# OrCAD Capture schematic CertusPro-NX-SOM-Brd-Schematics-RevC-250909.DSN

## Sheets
1 Title Page: title: Title Page; rev: 2.0; note: 305-PD-25-0961
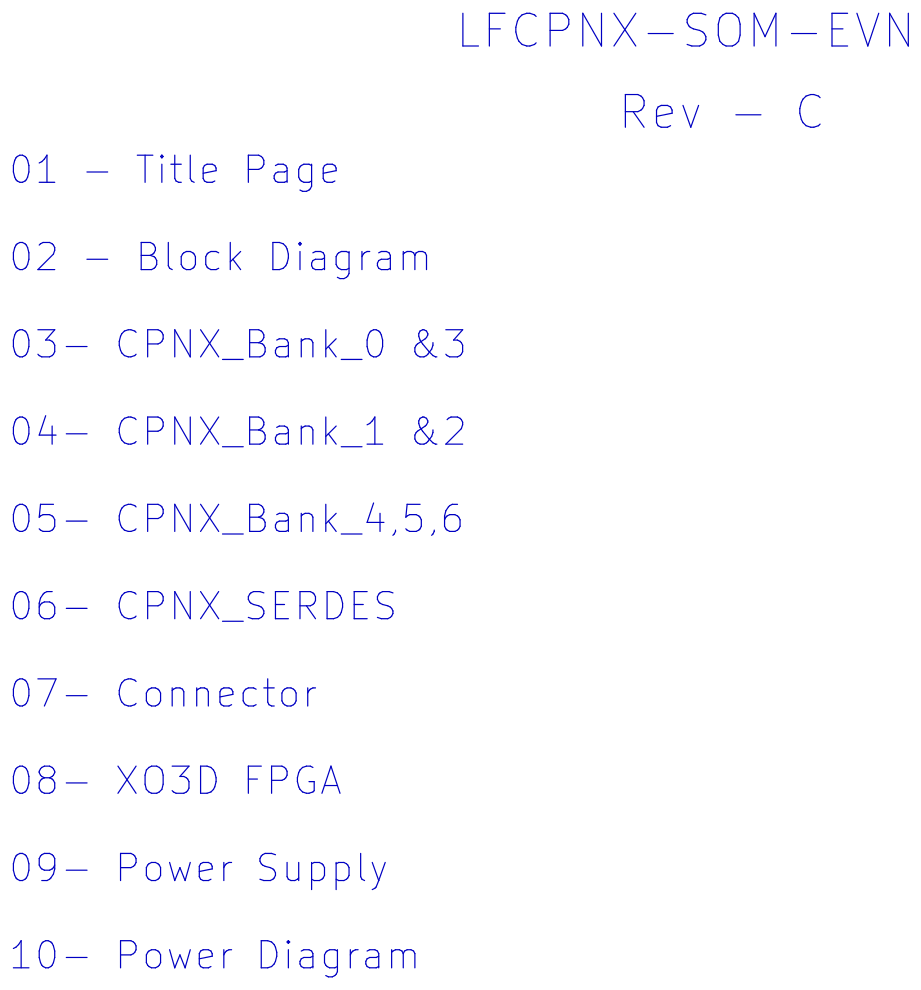
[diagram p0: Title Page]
2 Block Diagram: title: Block Diagram
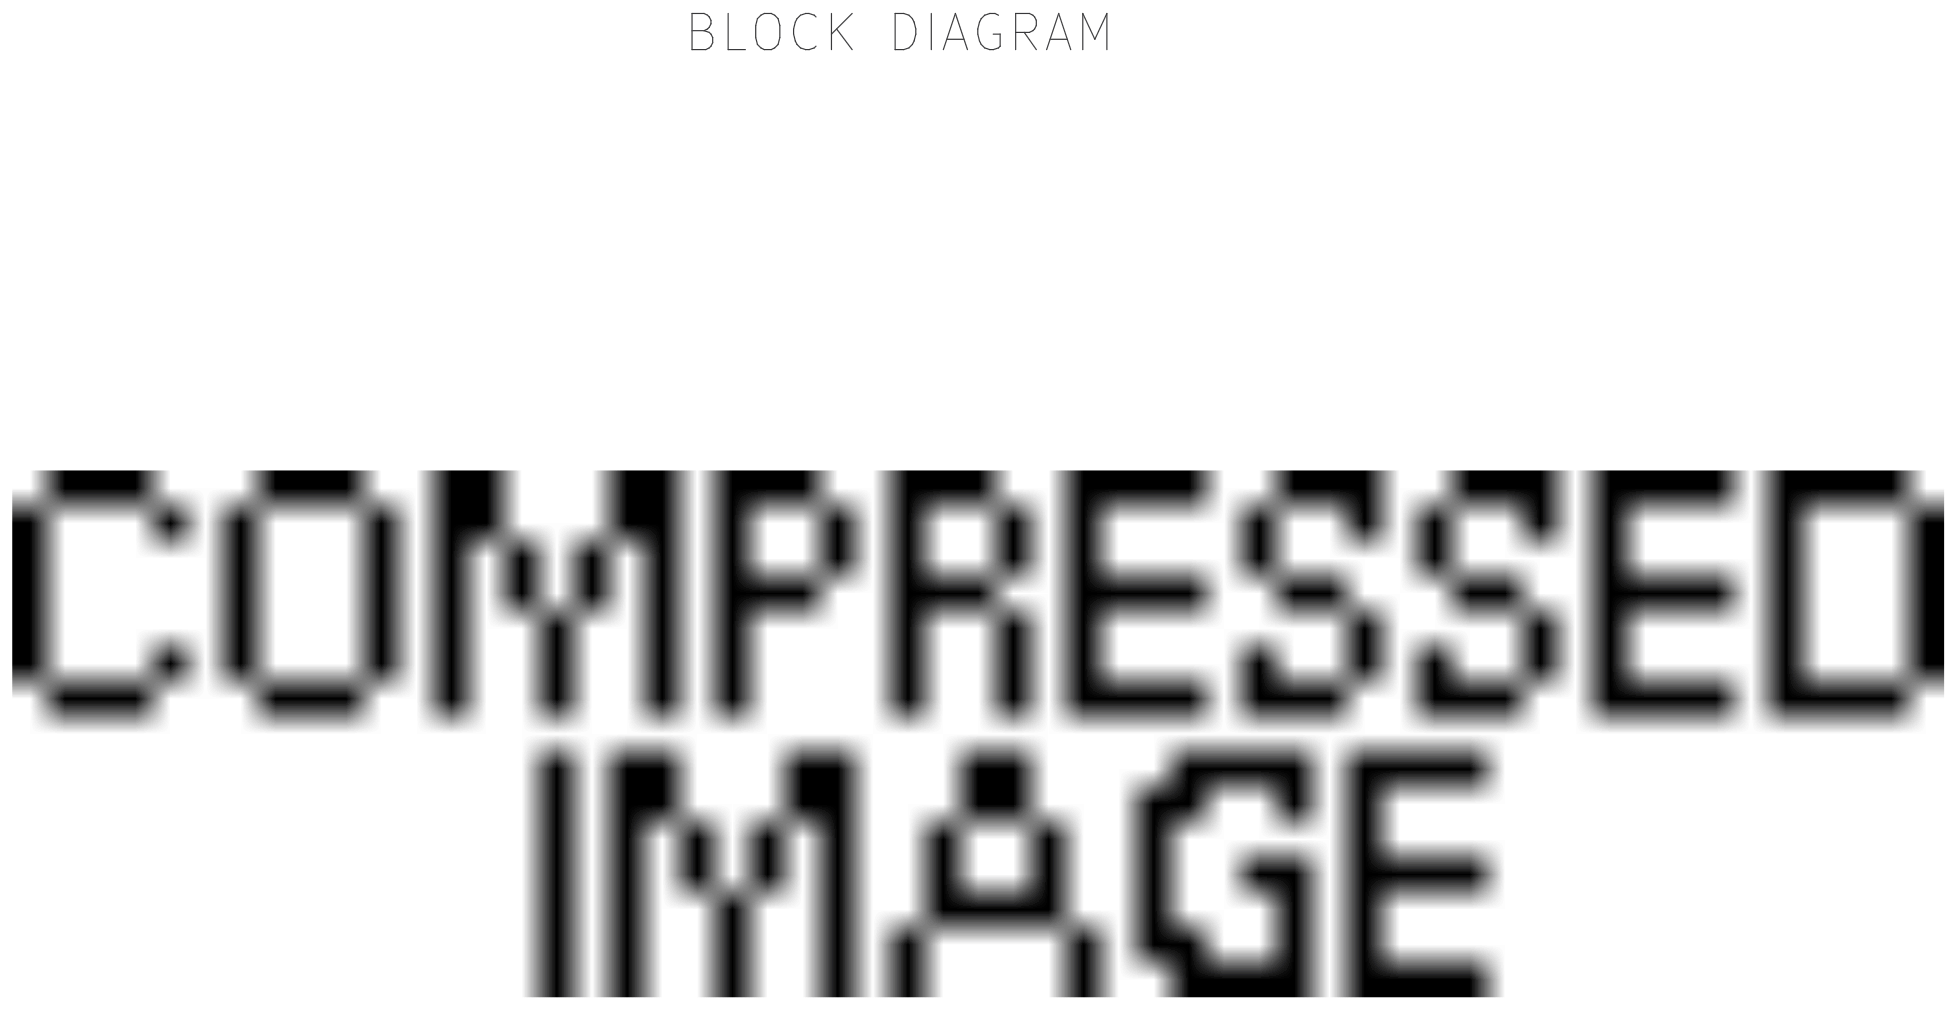
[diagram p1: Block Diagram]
3 CPNX_Bank_0: size B; title: CPNX_Bank_0_Config
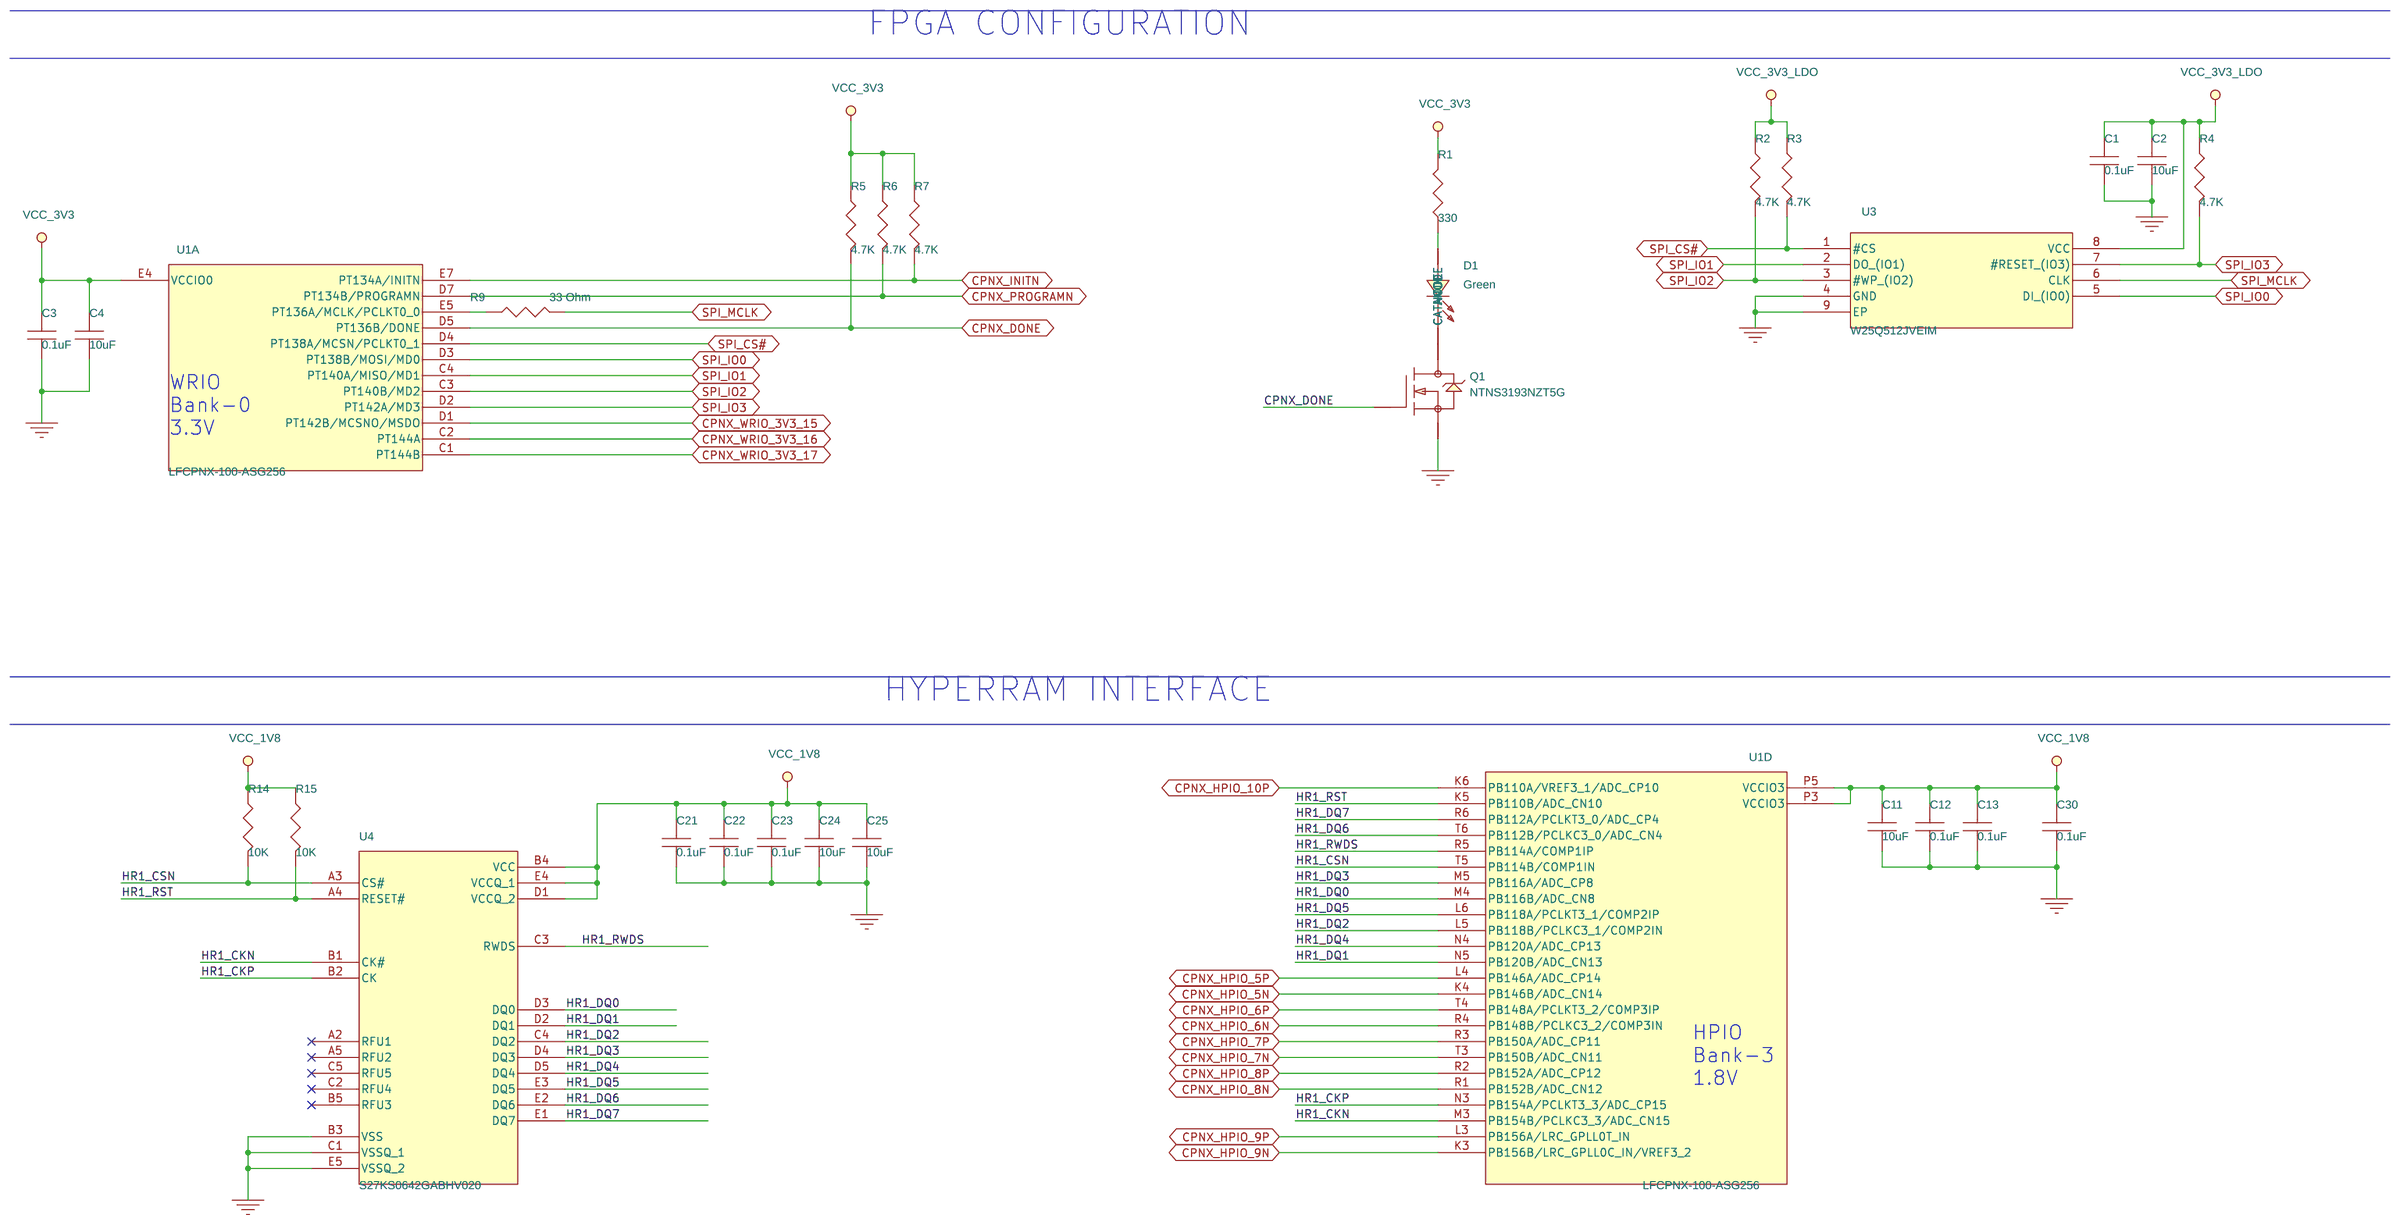
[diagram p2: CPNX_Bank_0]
4 CPNX_Bank_0,1,2: size B; title: CPNX JTAG GPIO
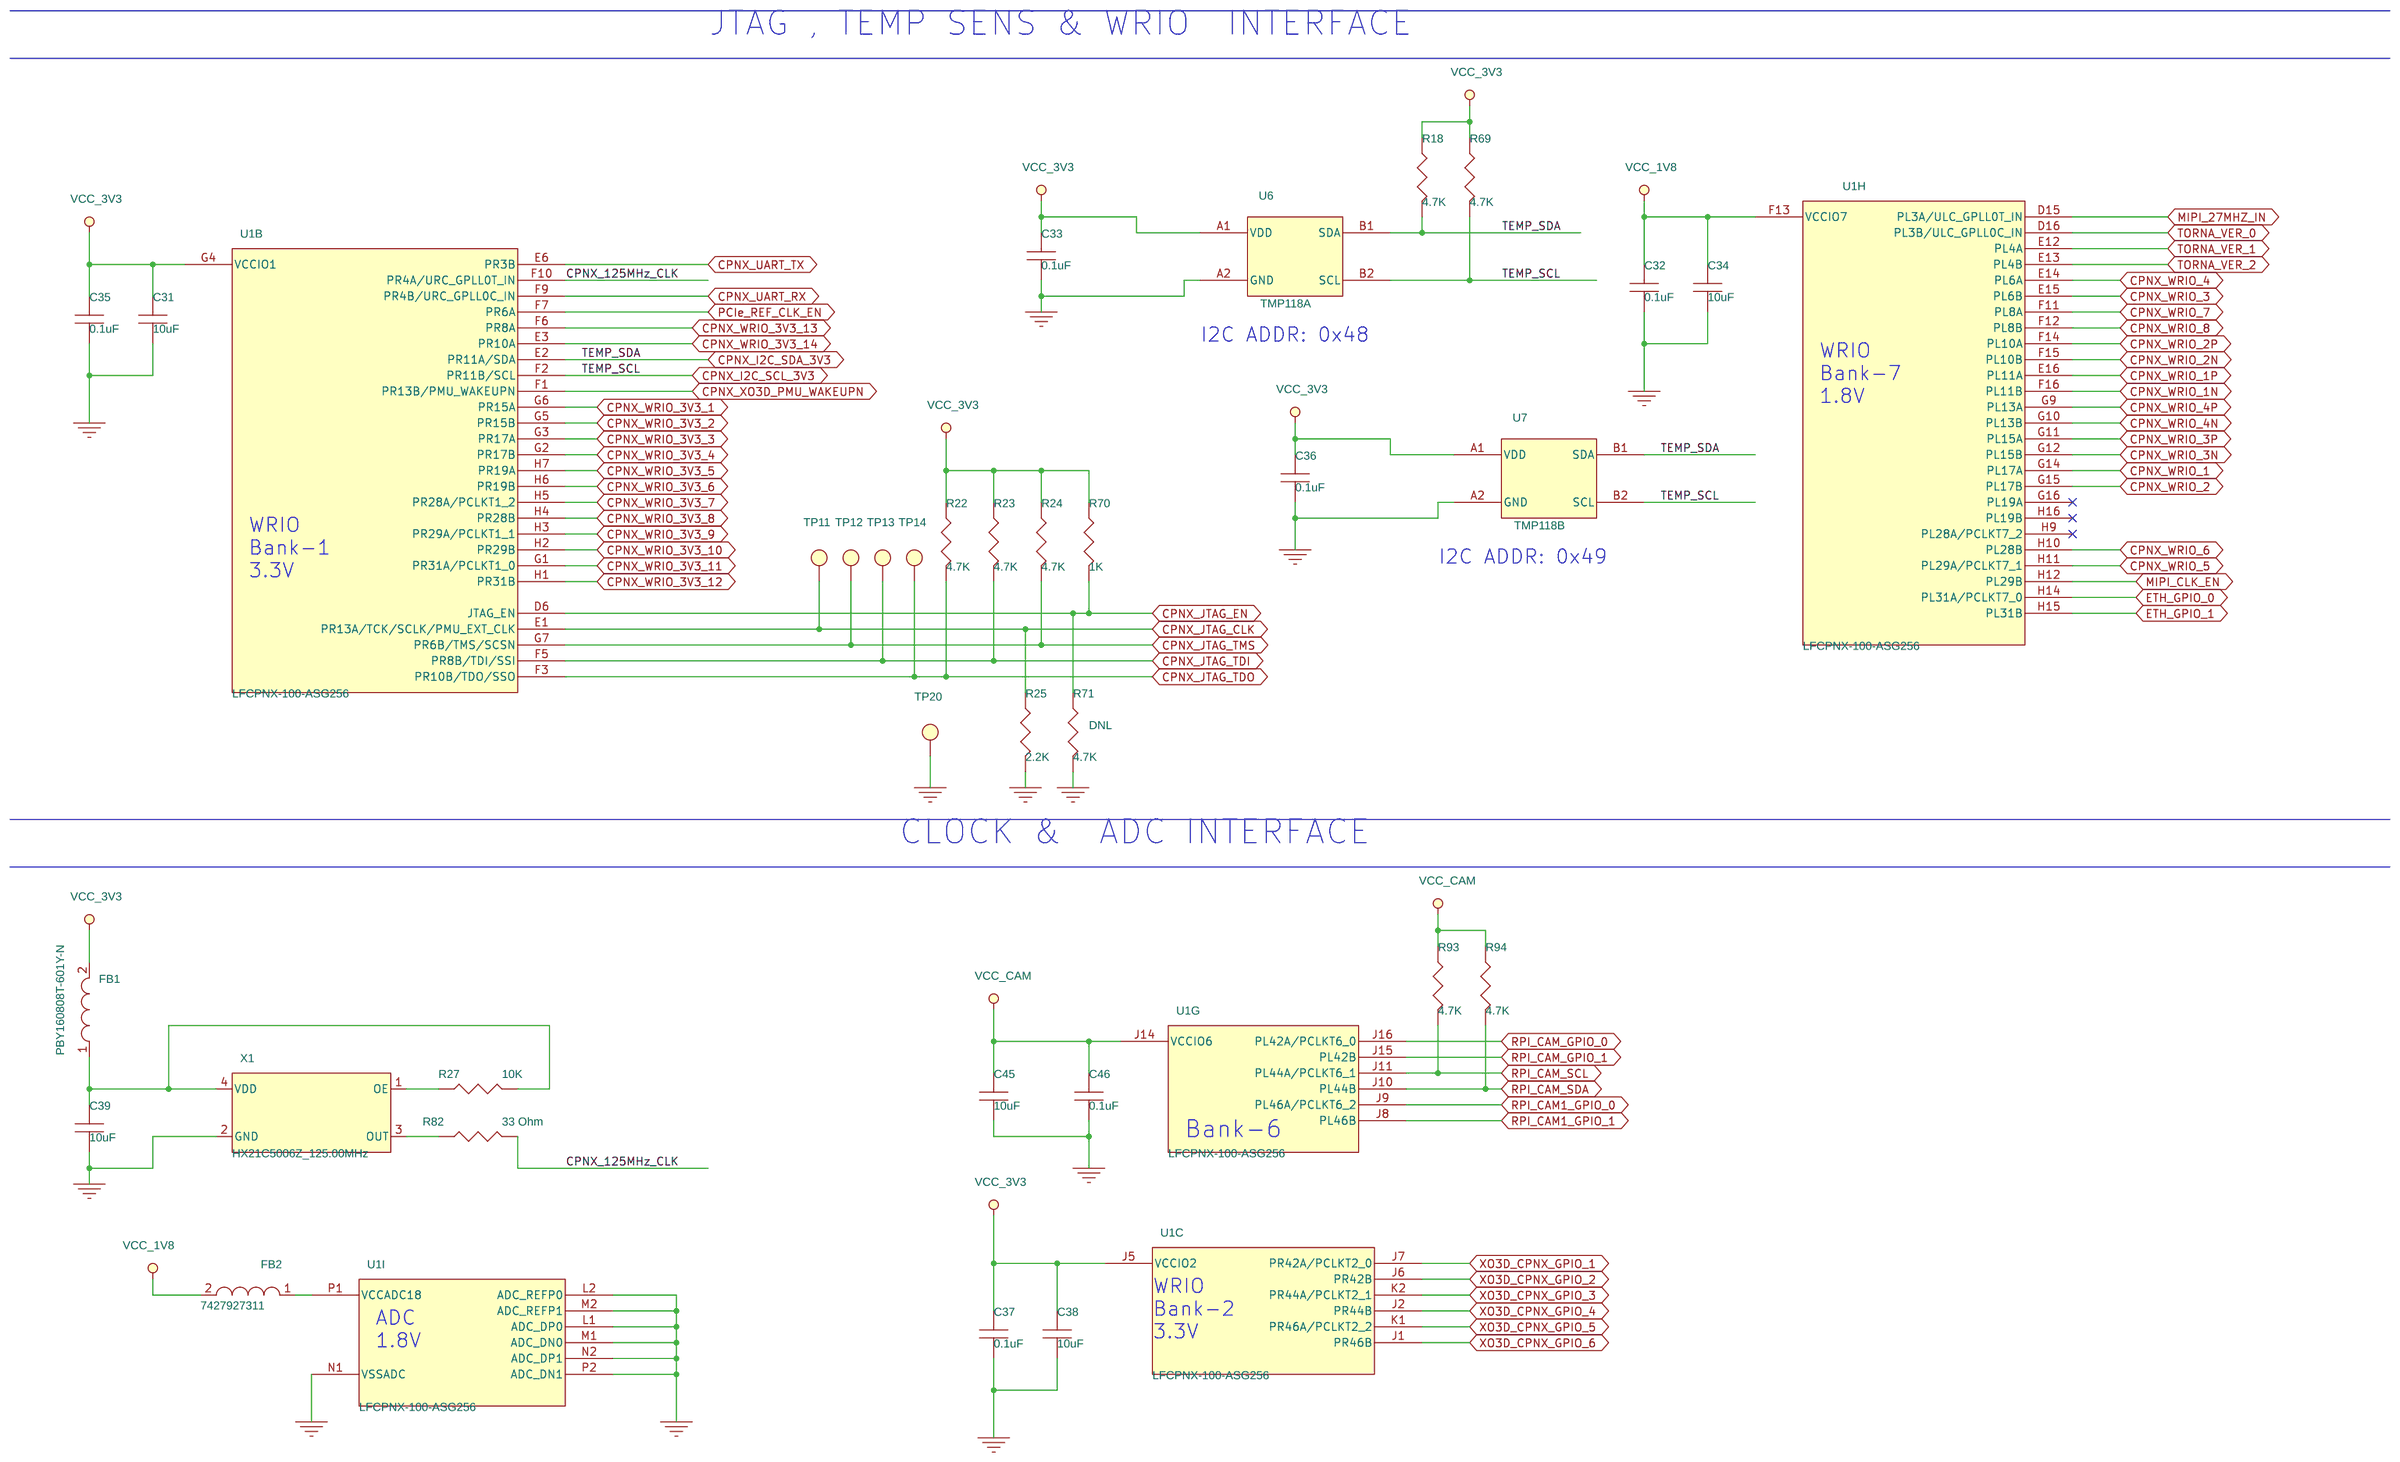
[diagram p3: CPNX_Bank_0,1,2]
5 CPNX_Bank-4 ,5 ,6: size B; title: RPC DRAM's
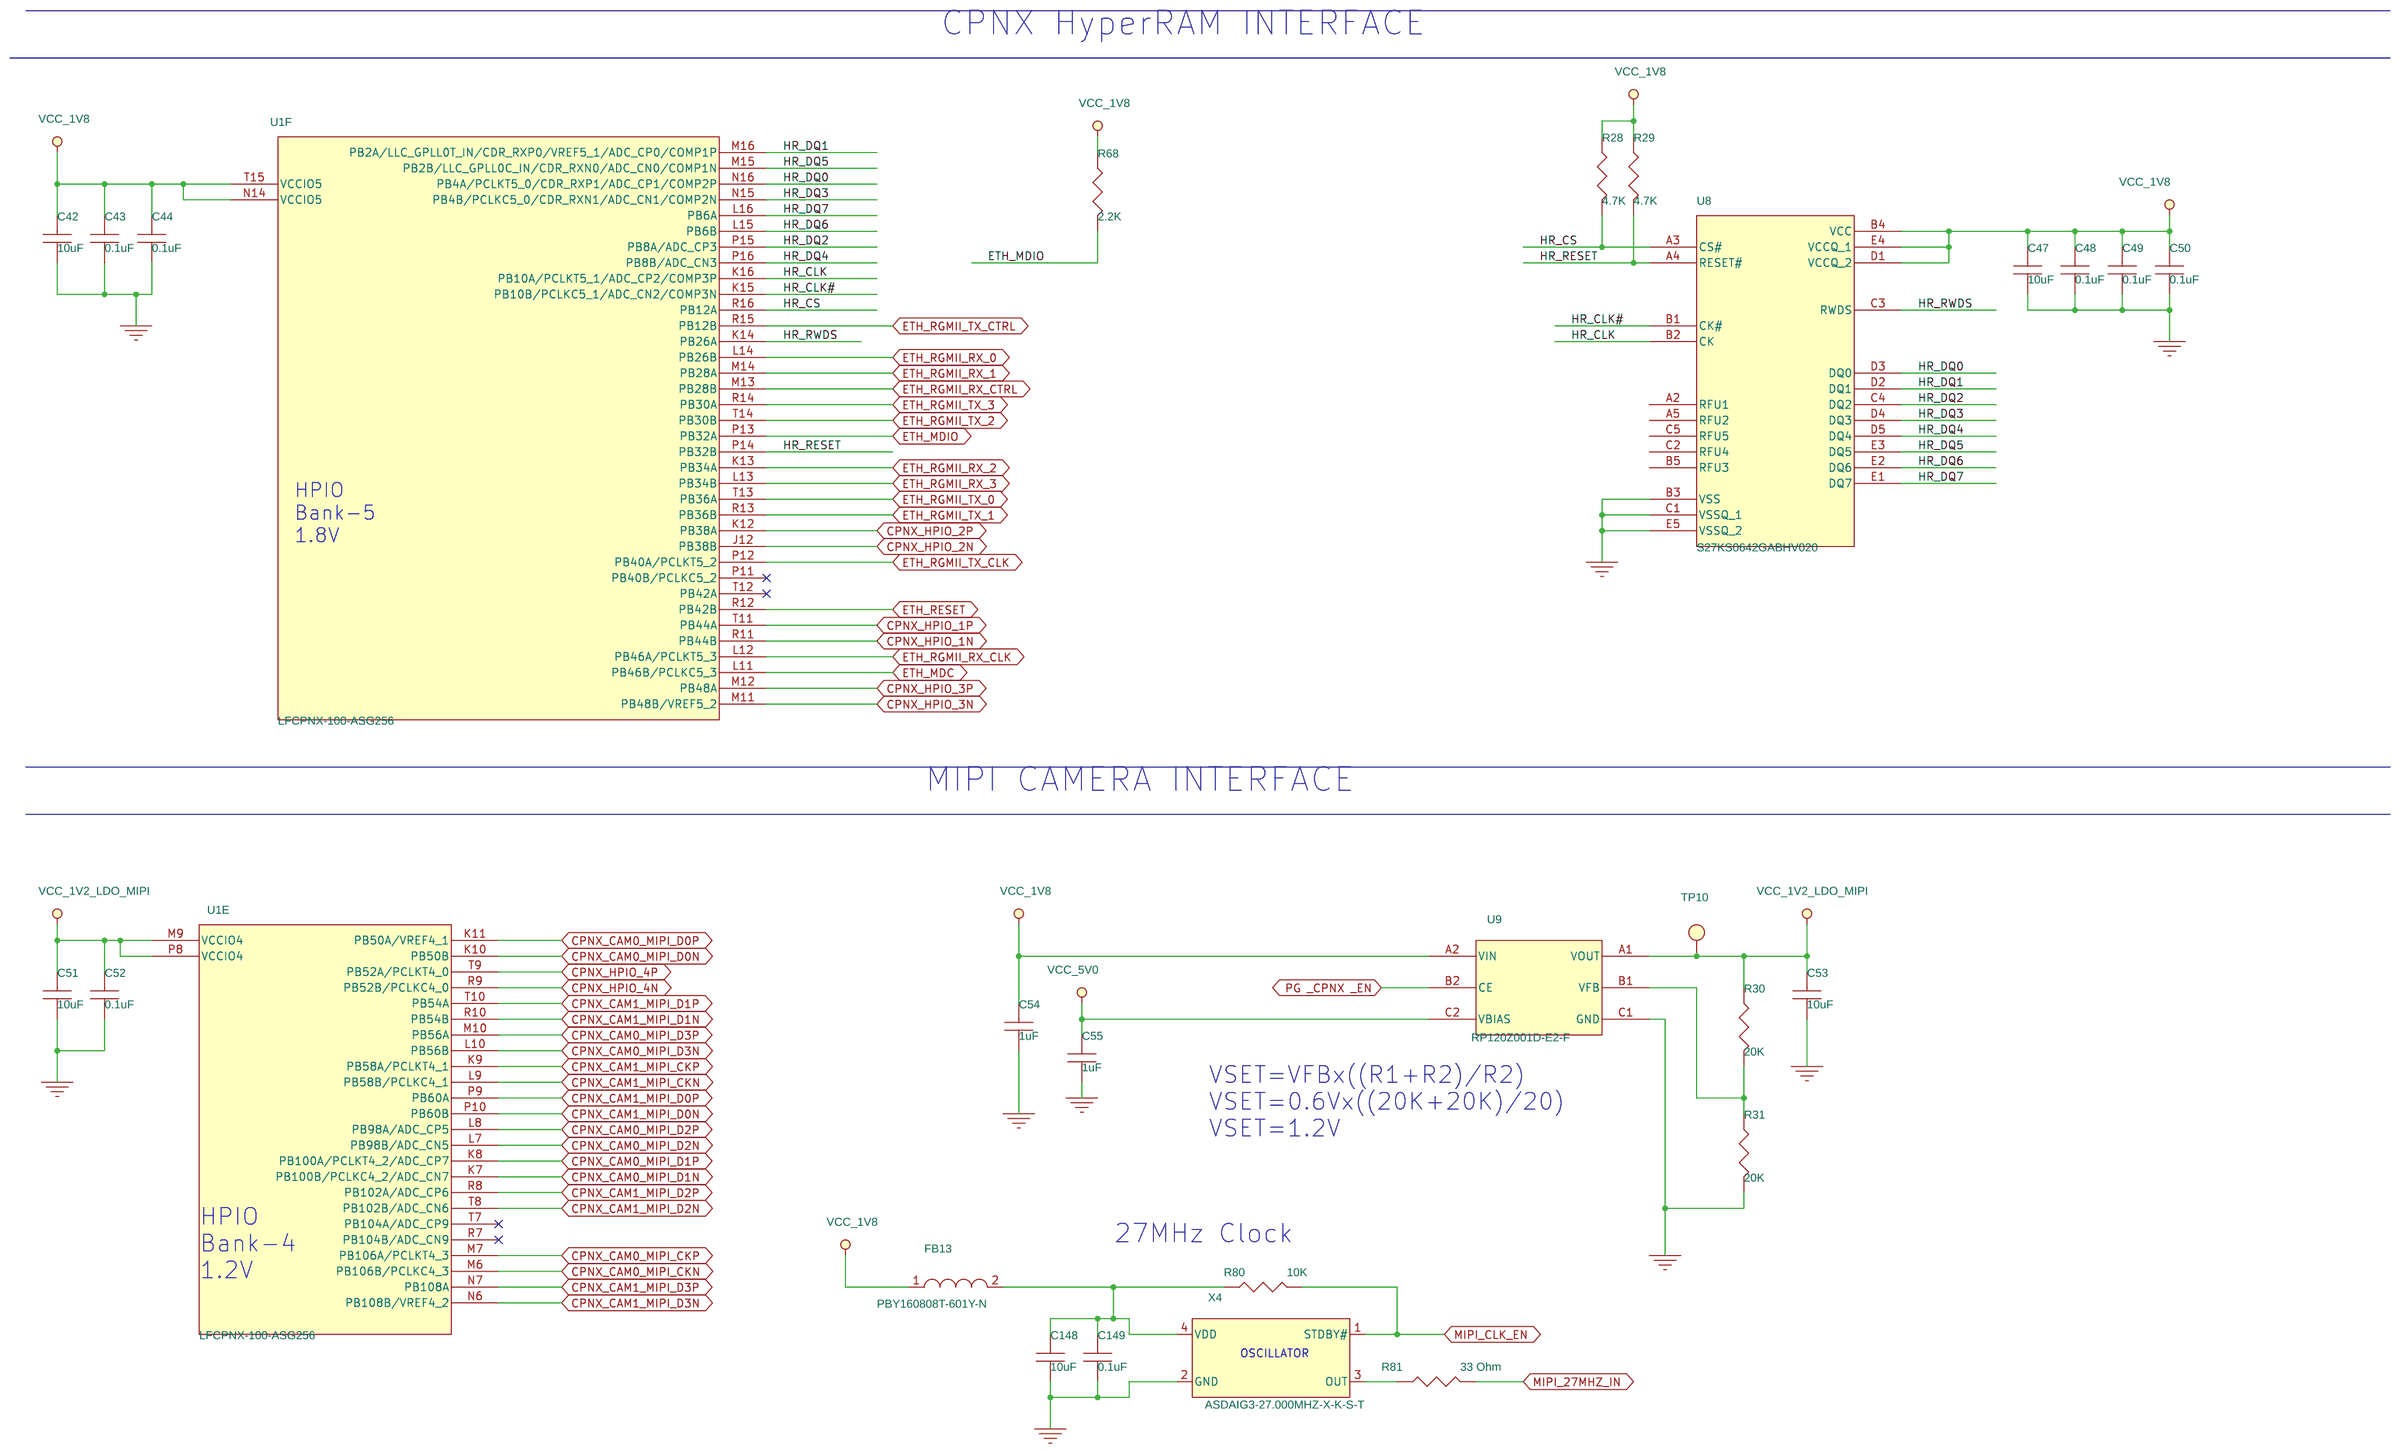
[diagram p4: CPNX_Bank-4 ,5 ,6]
6 CPNX SERDES: size B; title: CPNX SERDES
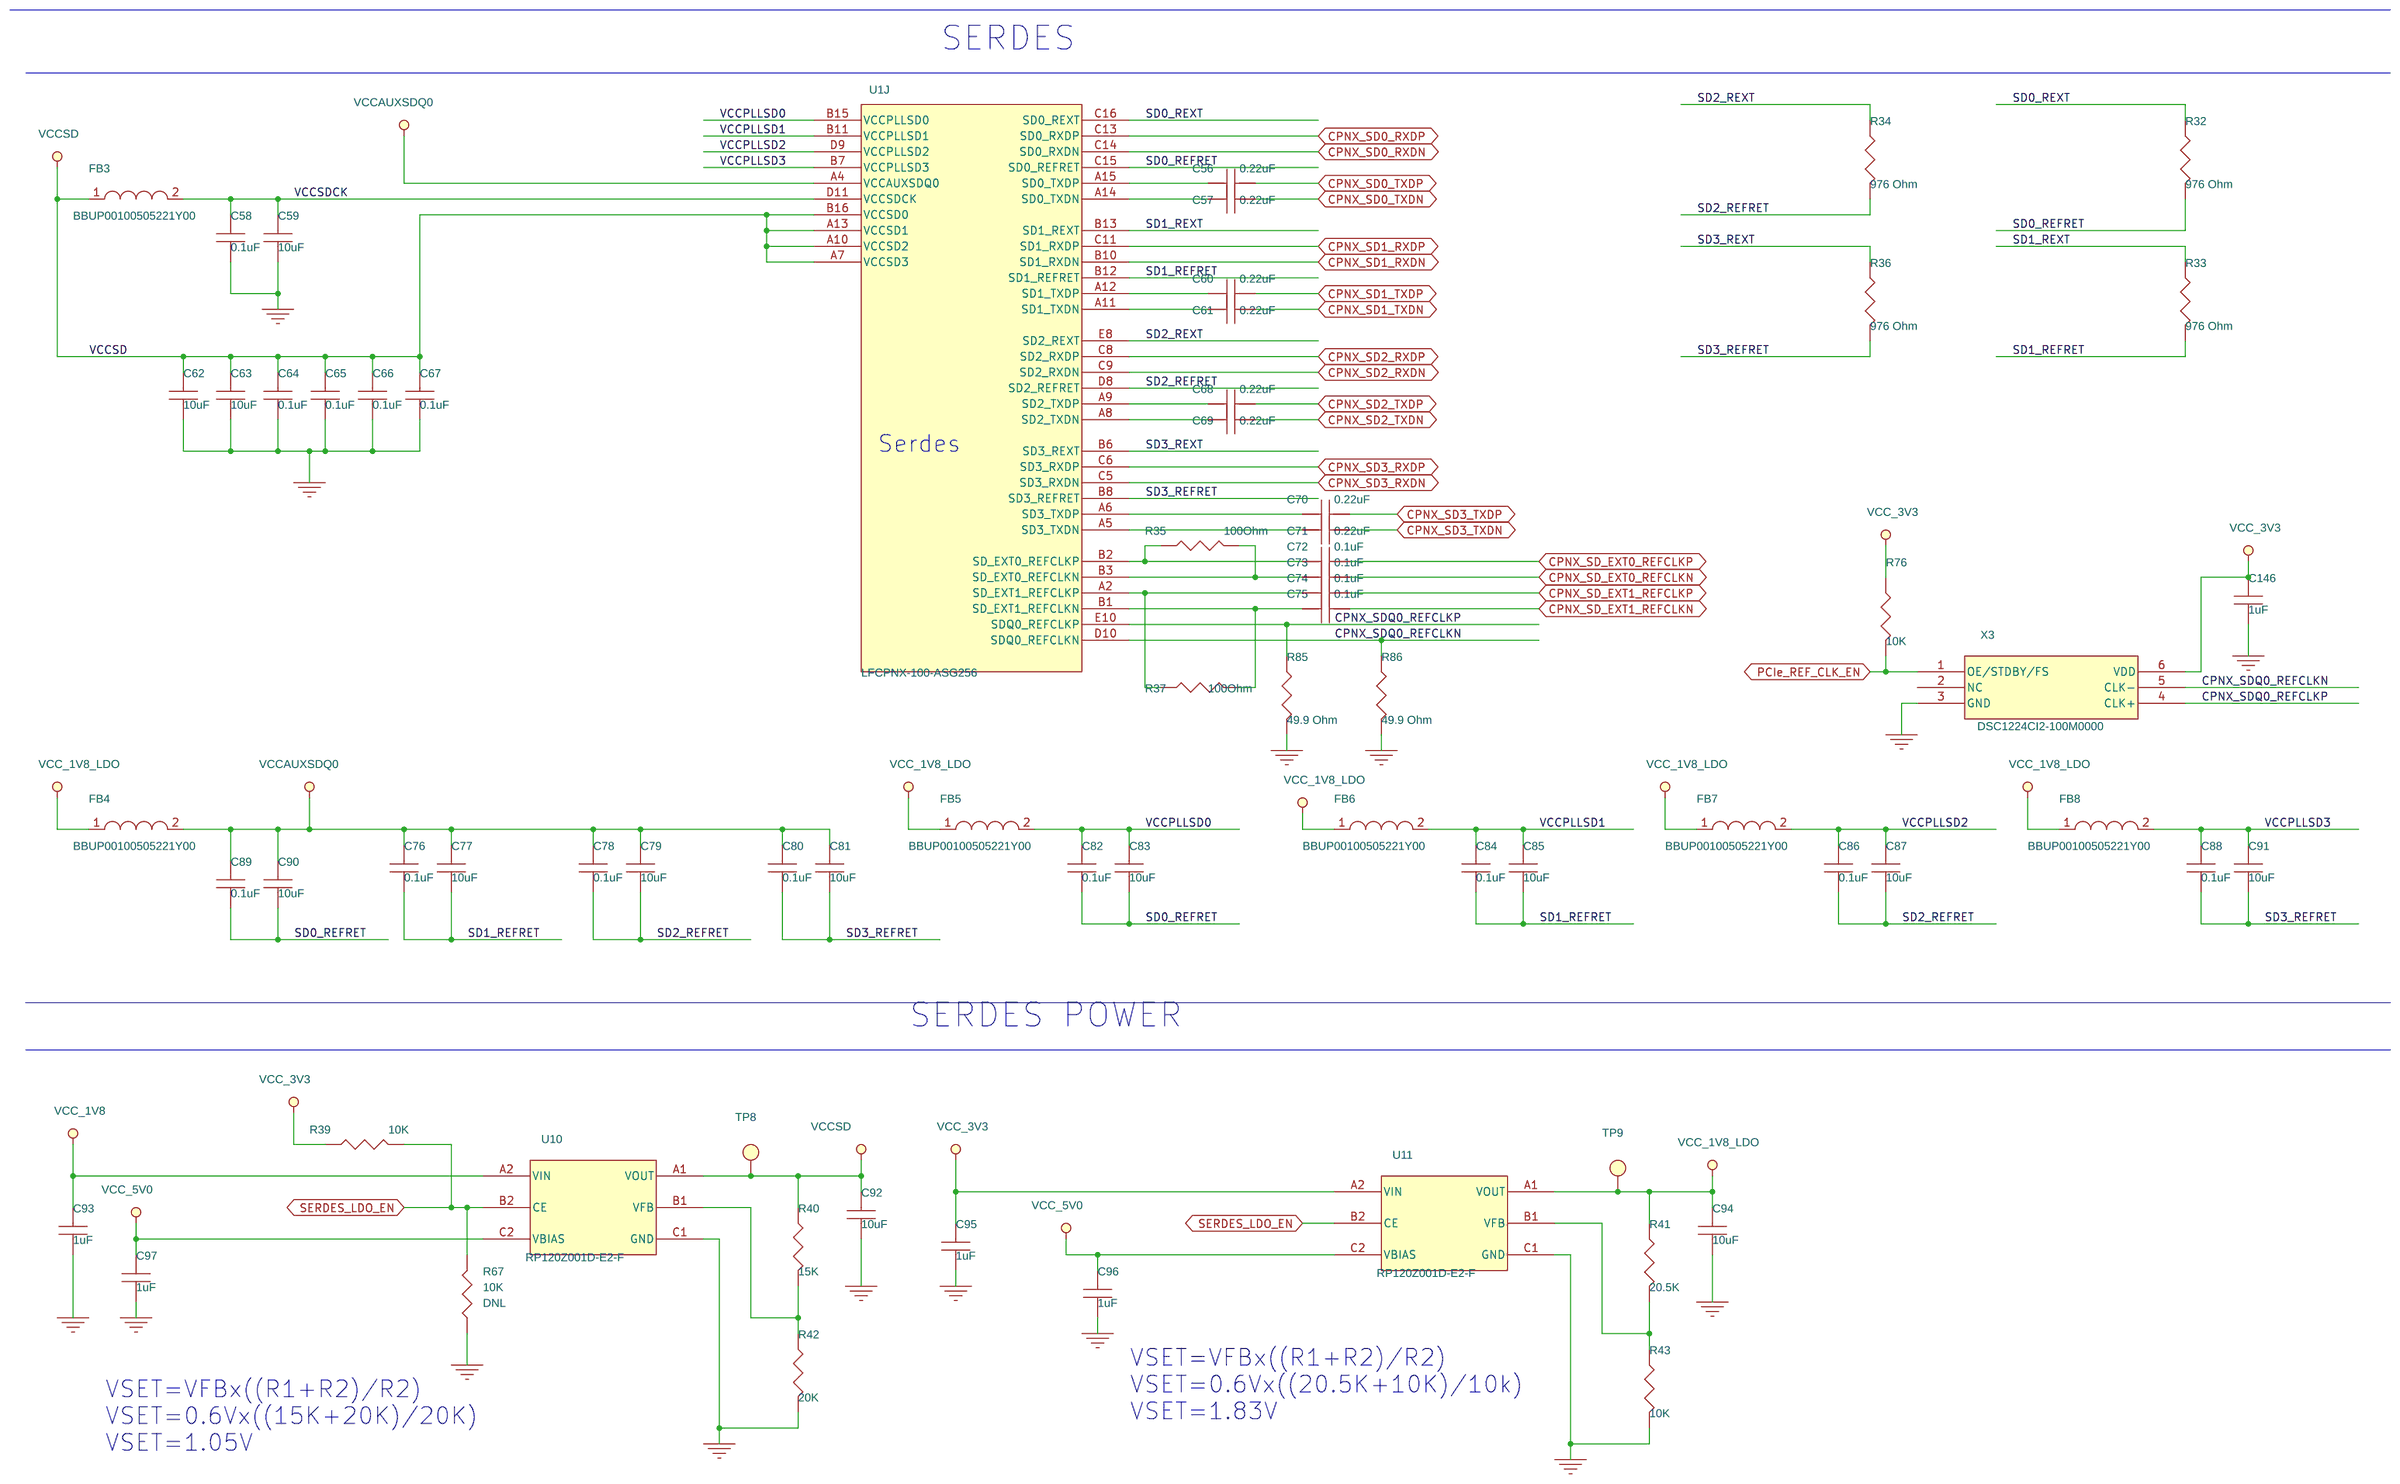
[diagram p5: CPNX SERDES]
7 Connector: size B; title: B2B Connector
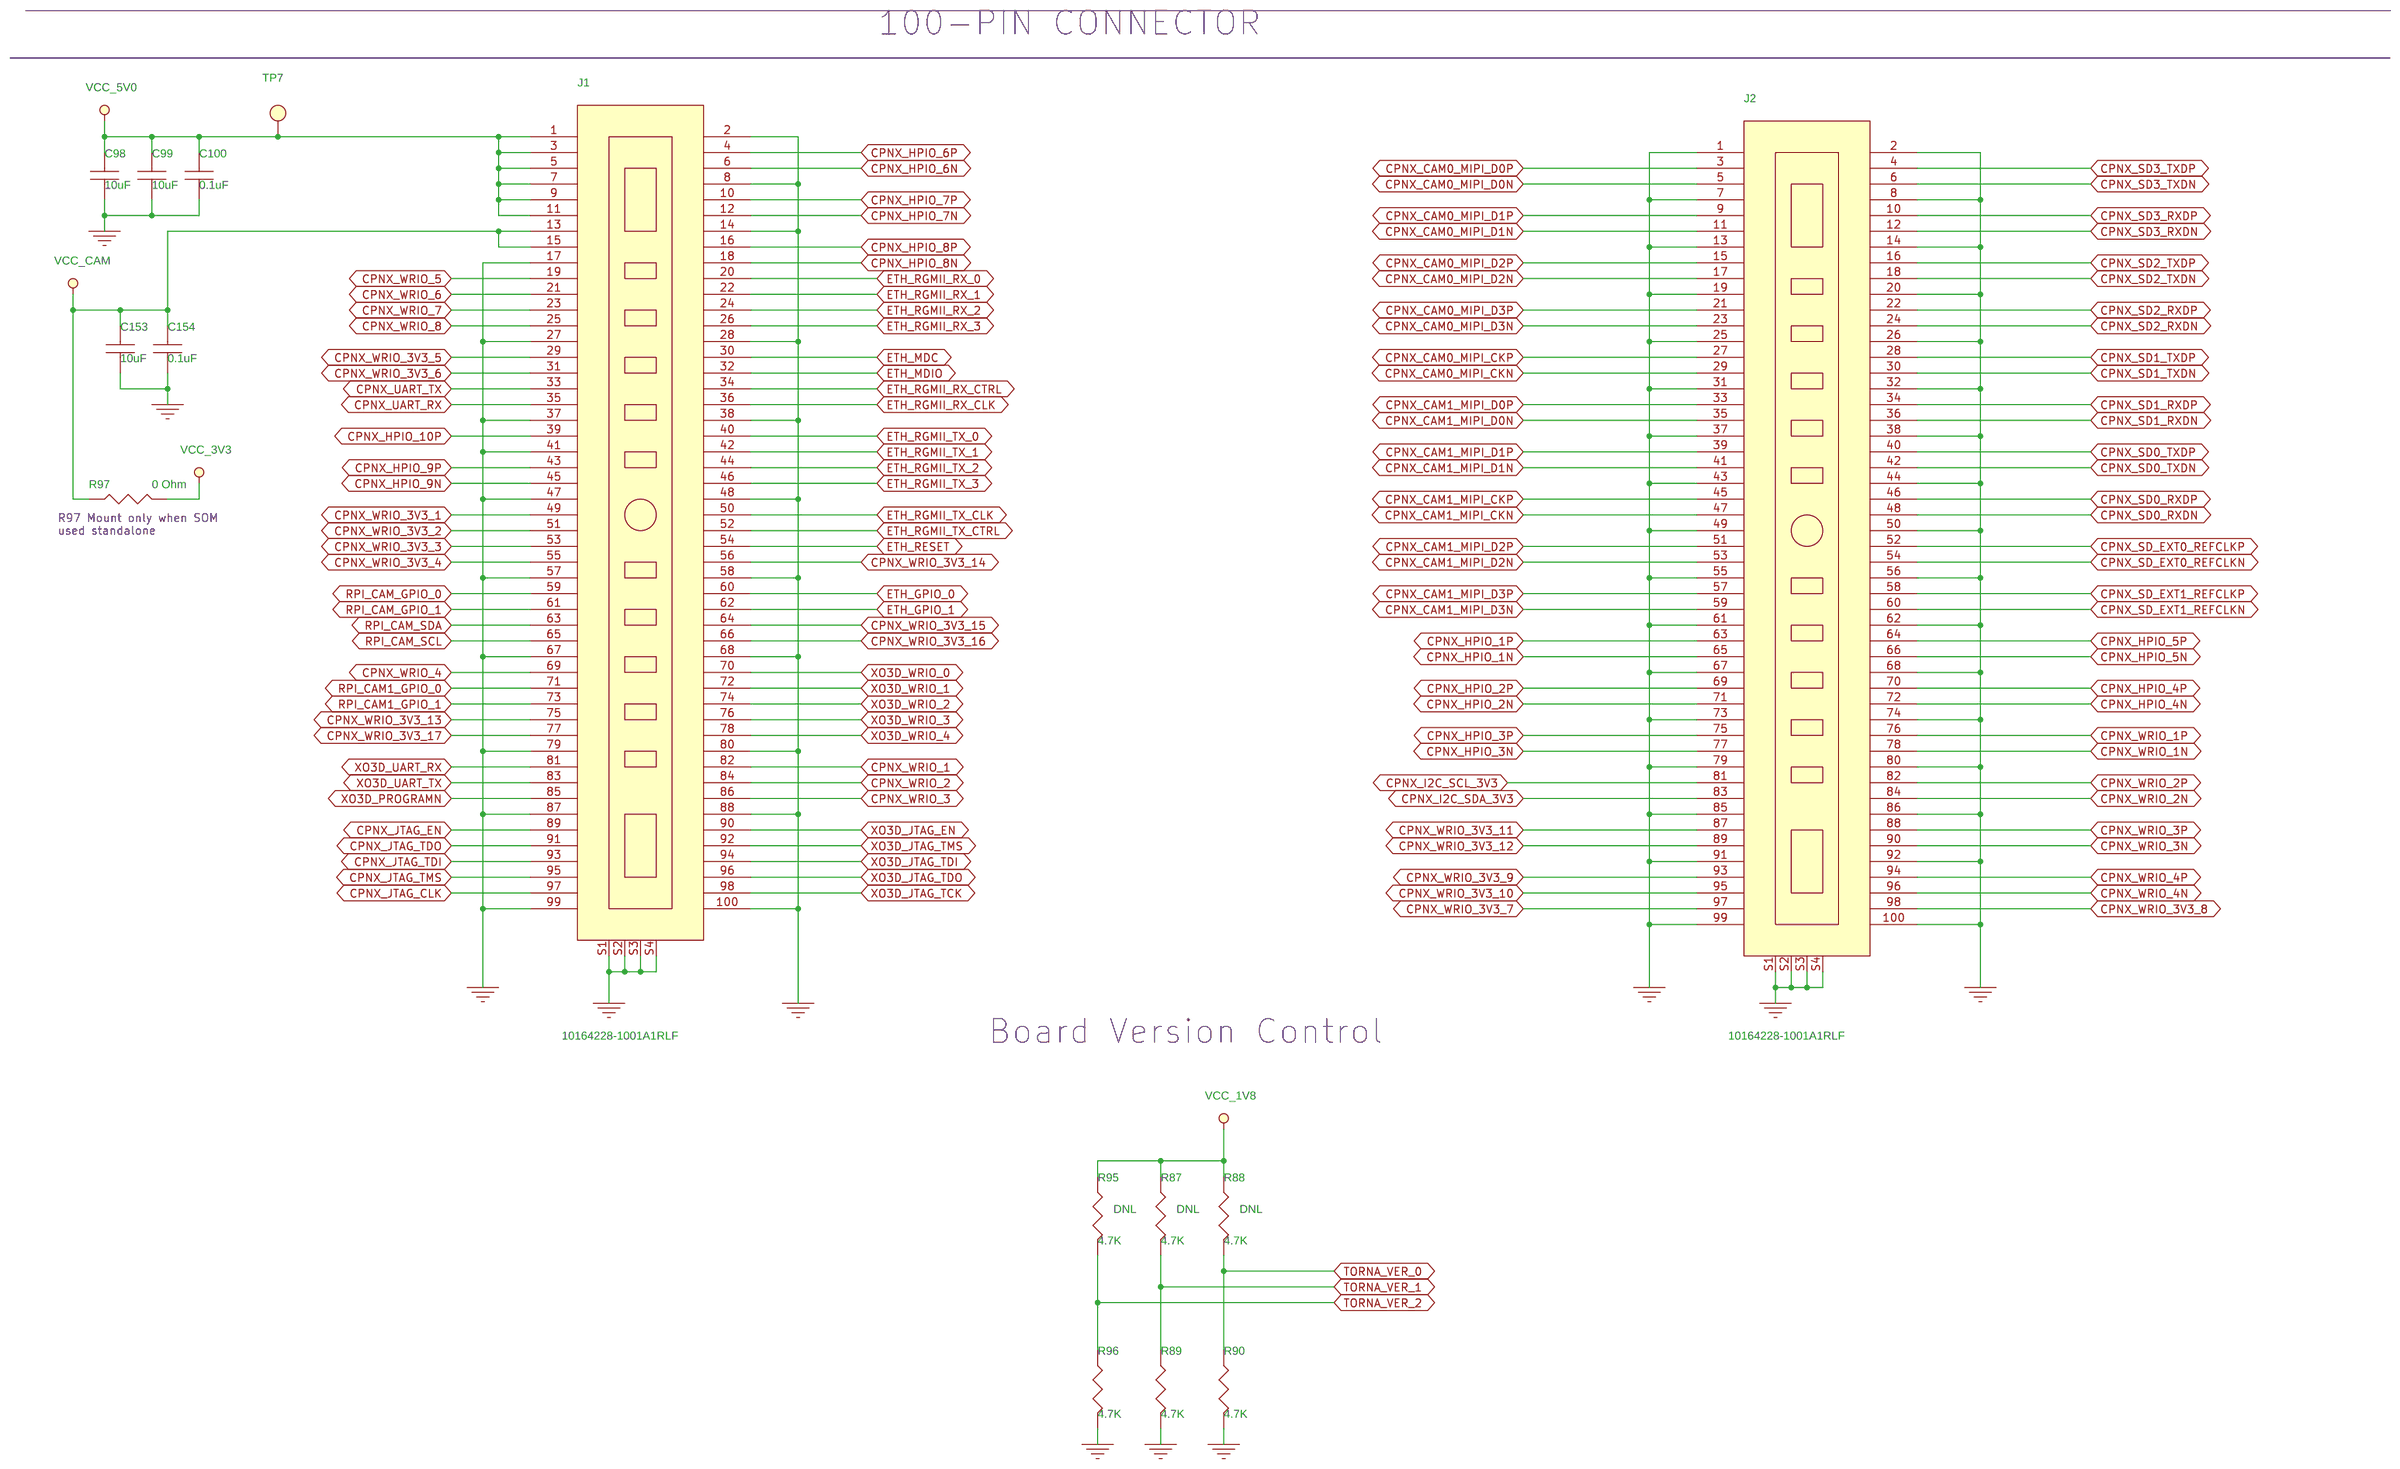
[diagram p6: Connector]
8 XO3D FPGA: size B; title: XO3D FPGA
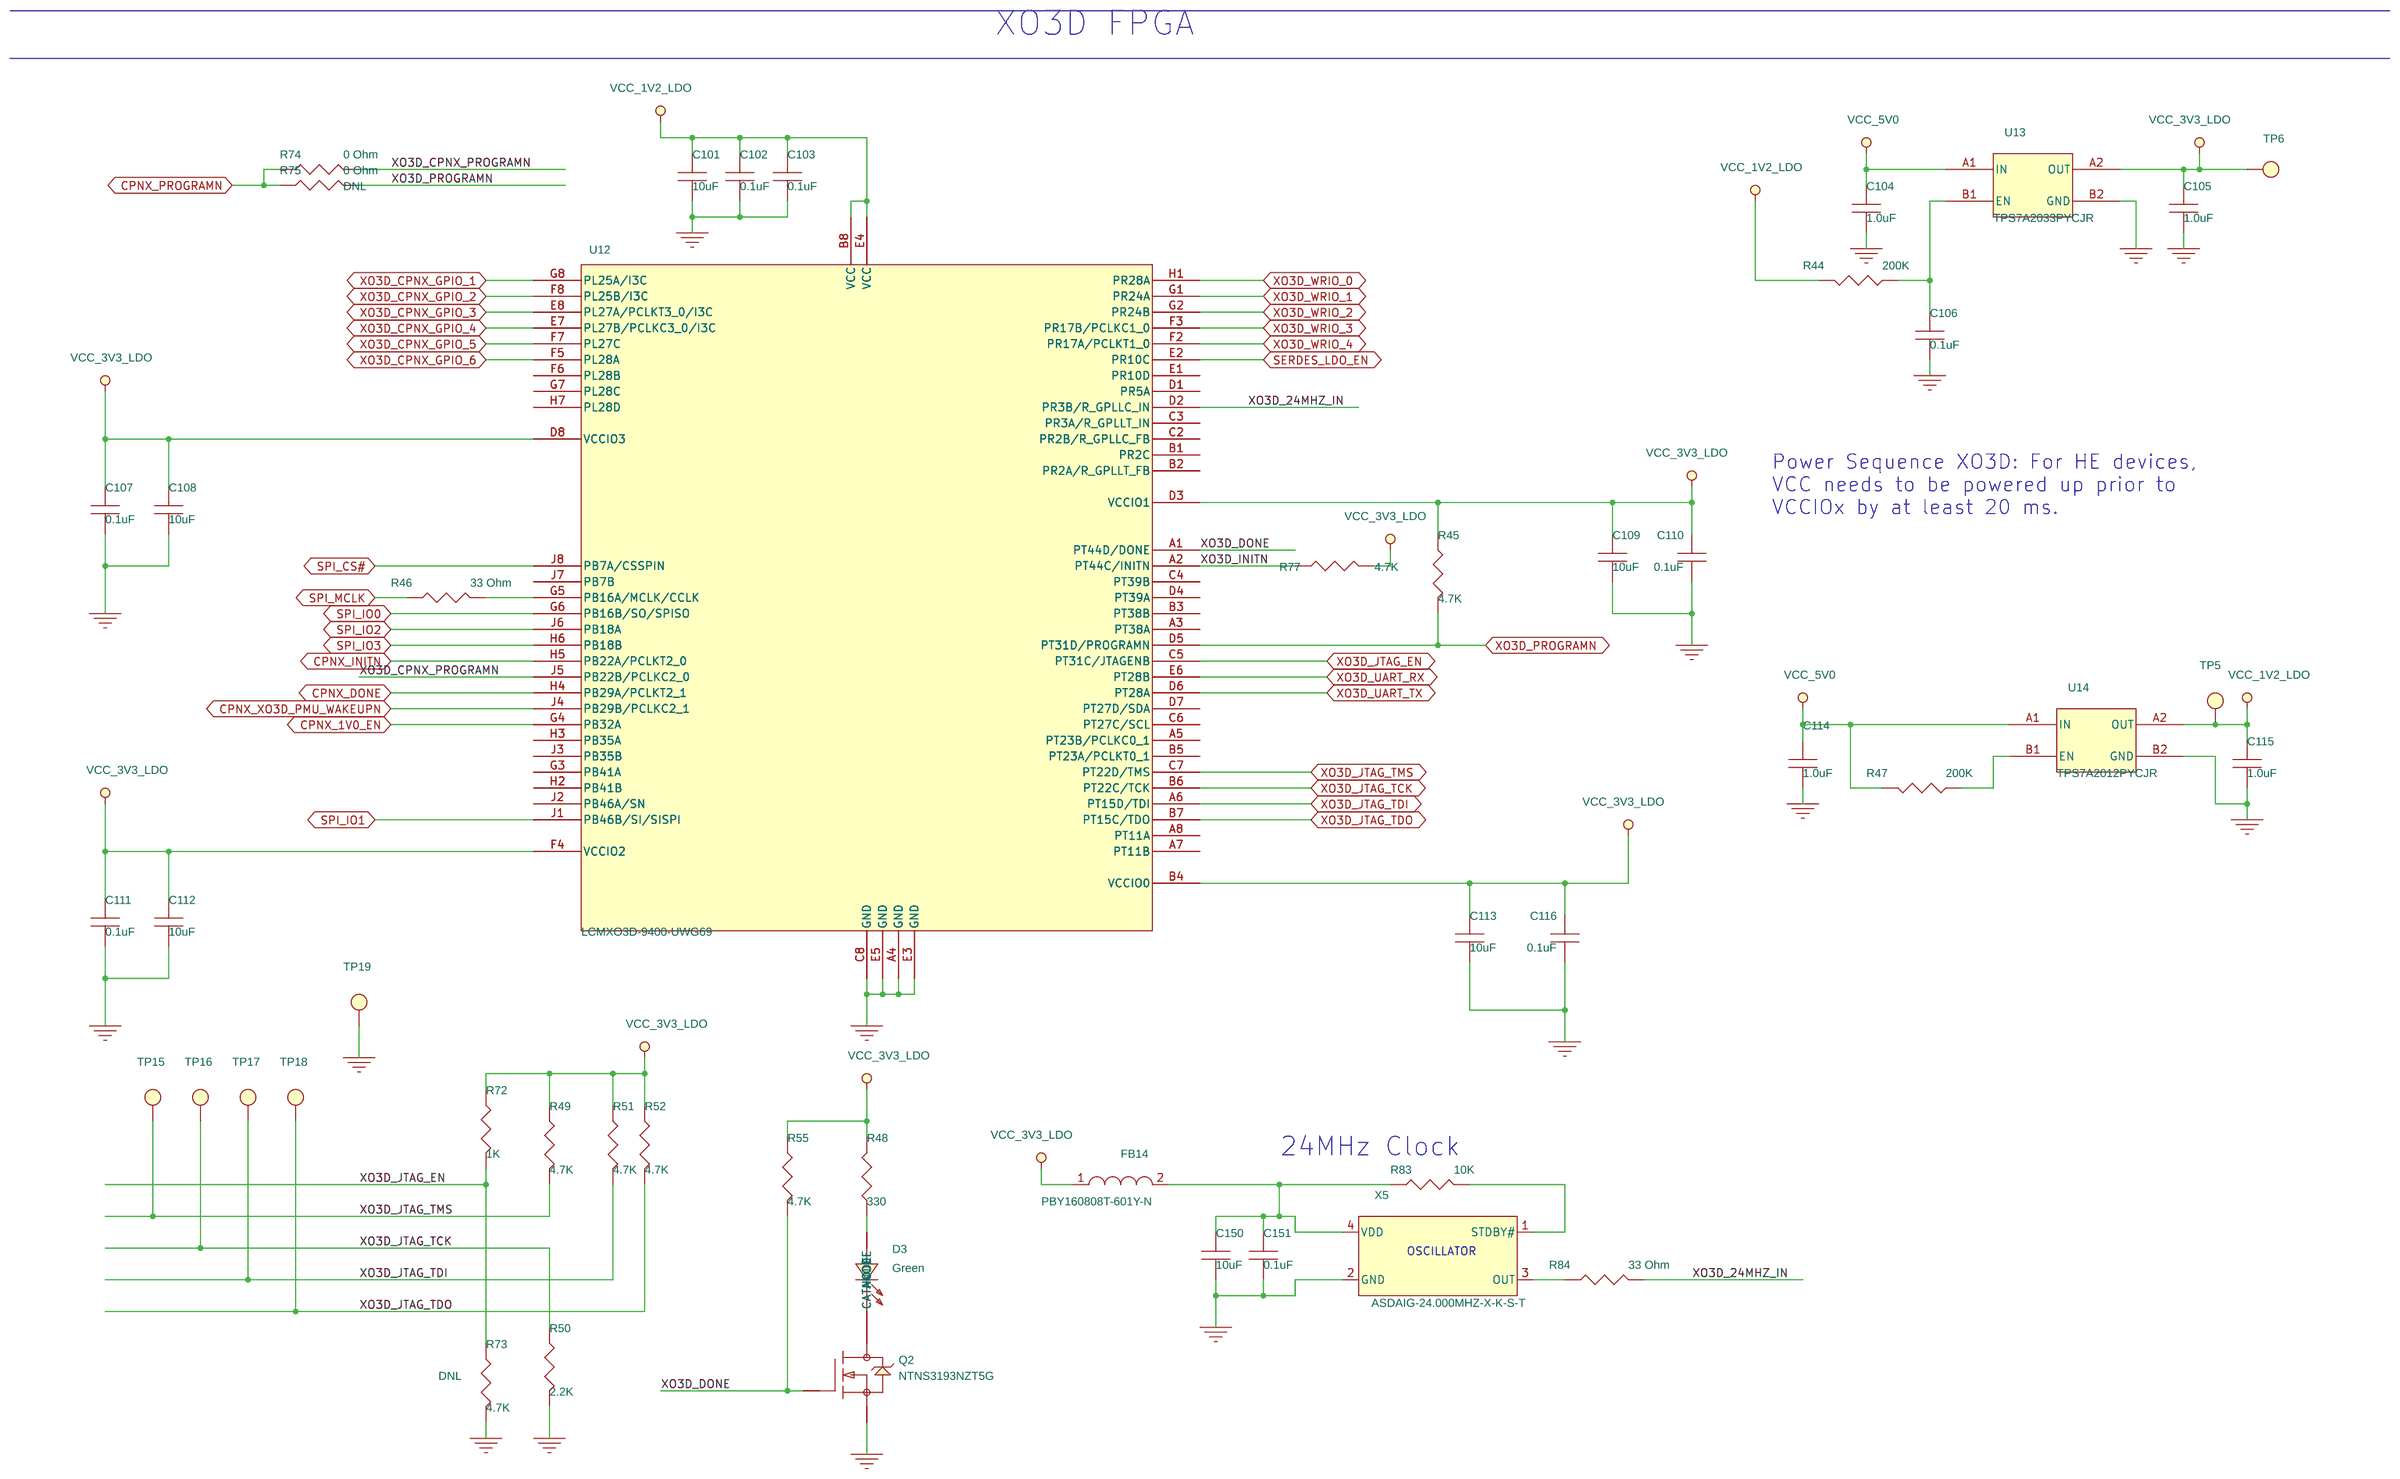
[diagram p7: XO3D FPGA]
9 Power Supply: size B; title: Power Supply
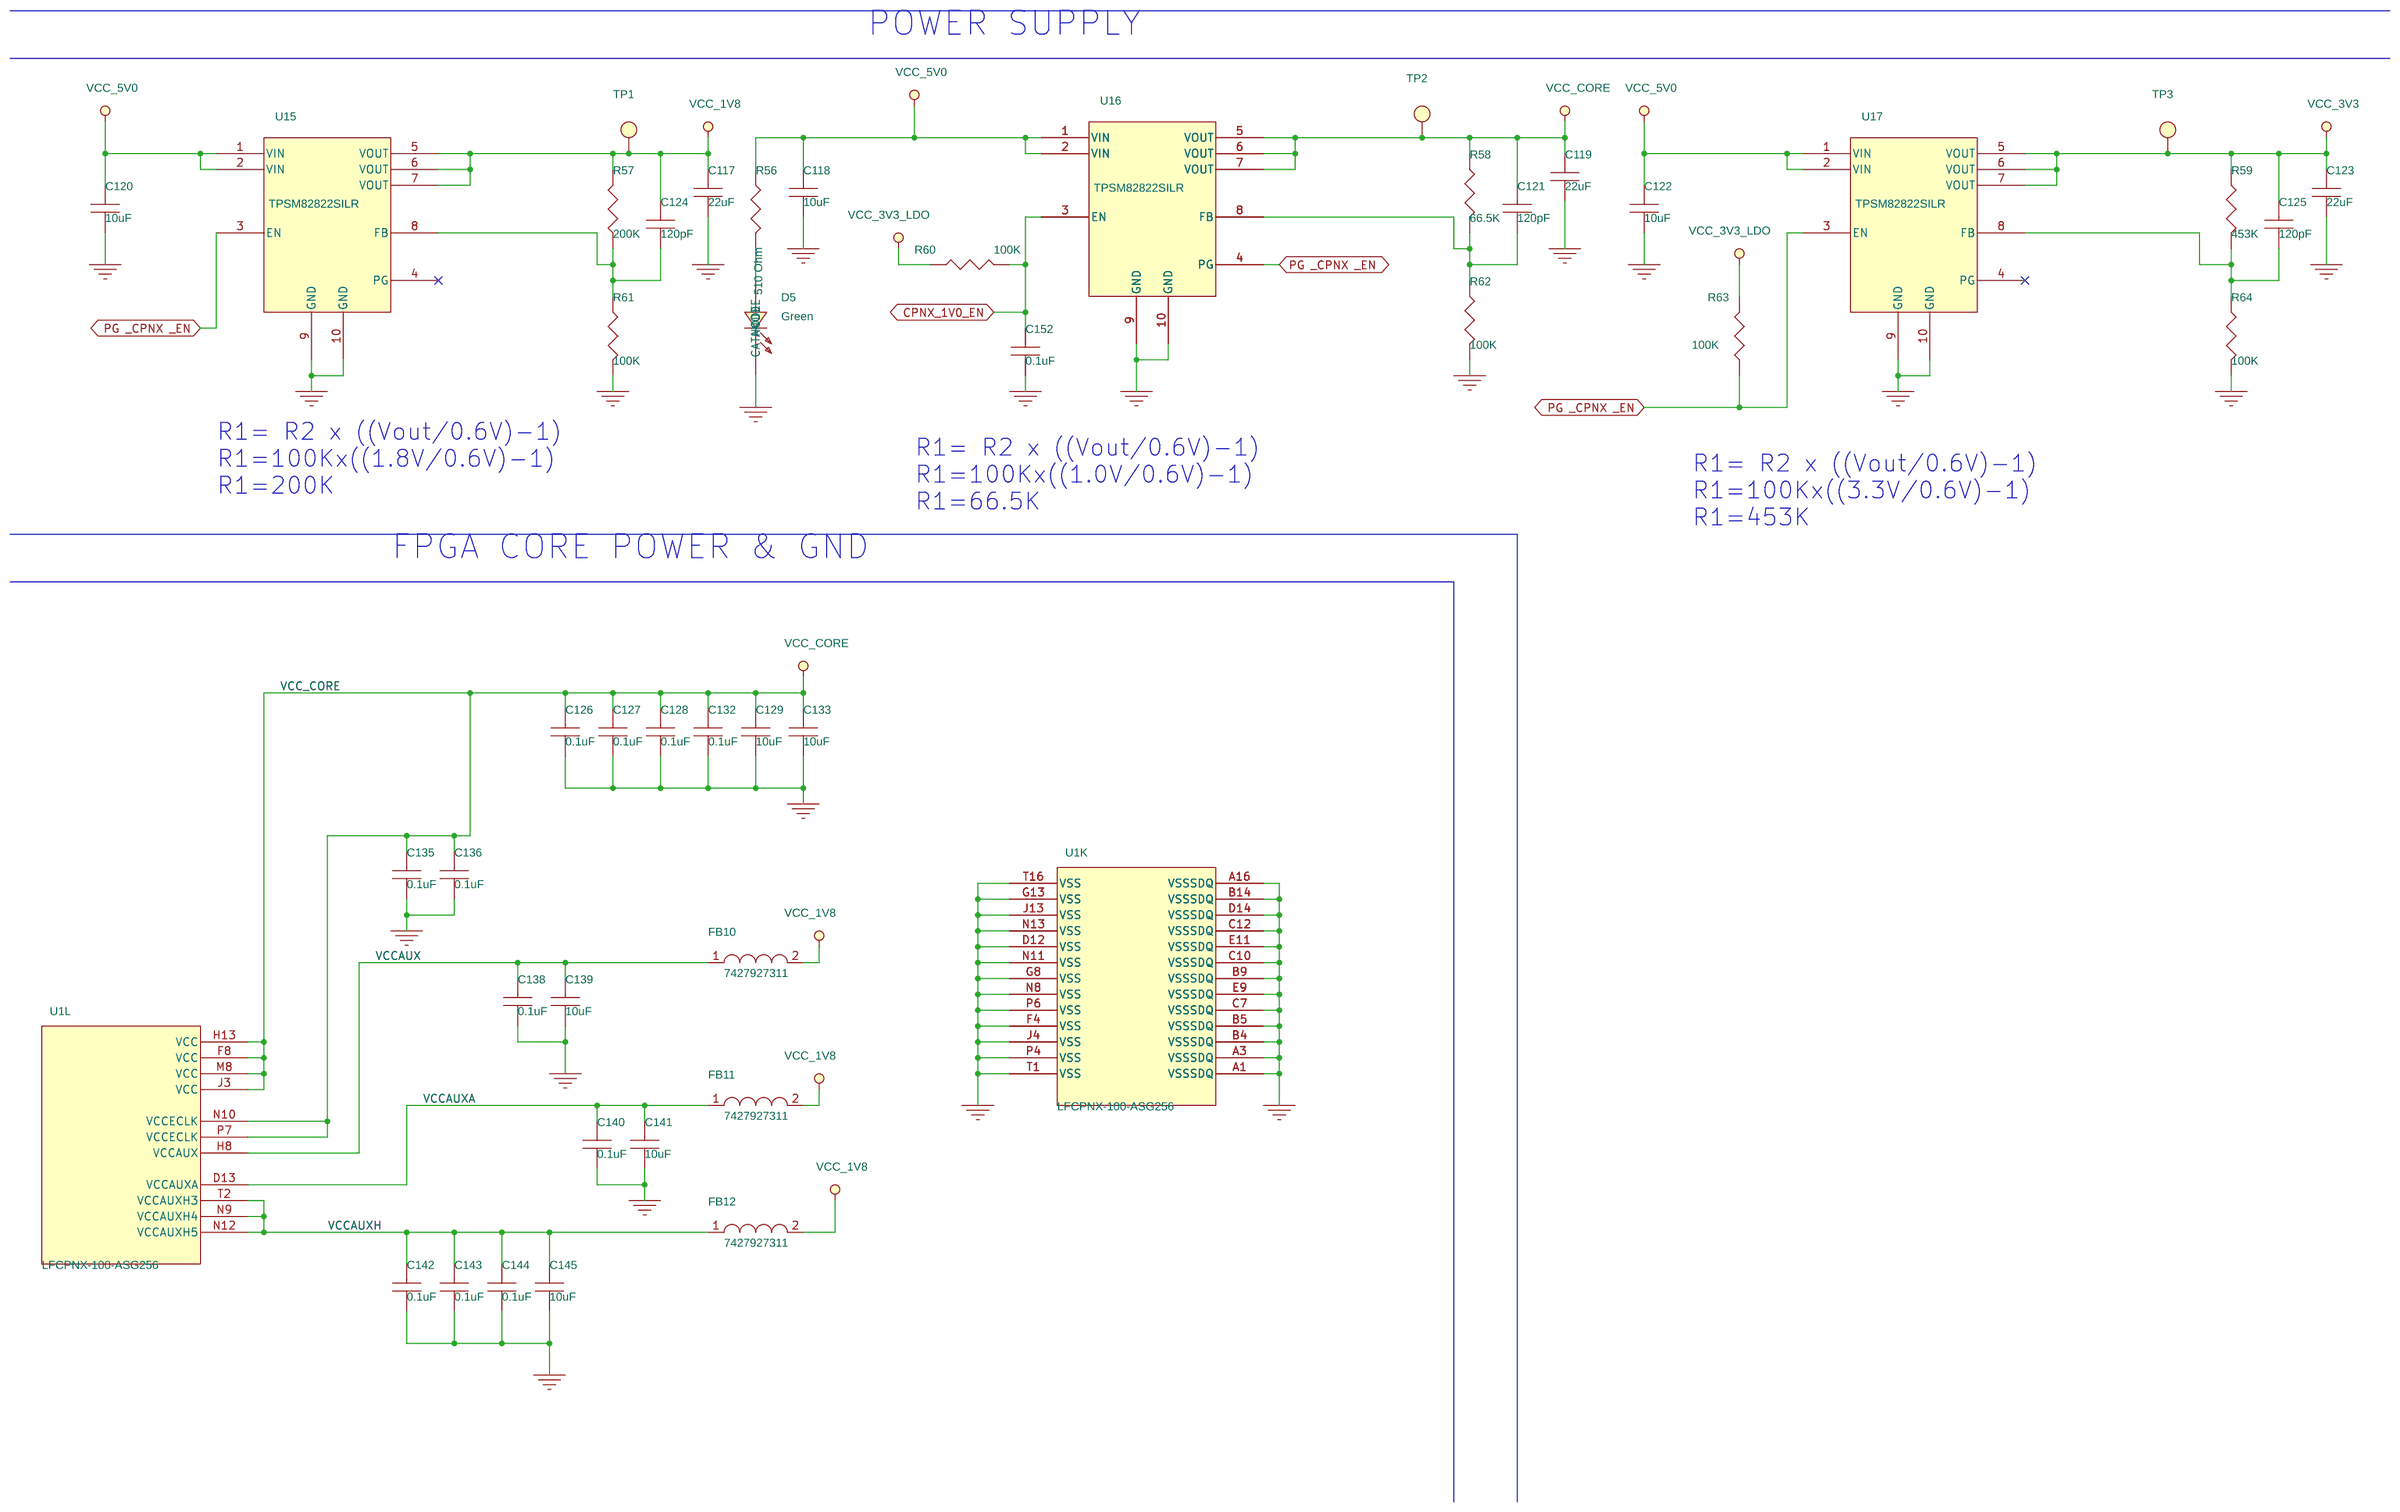
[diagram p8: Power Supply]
10 Power Diagram: title: Power Diagram
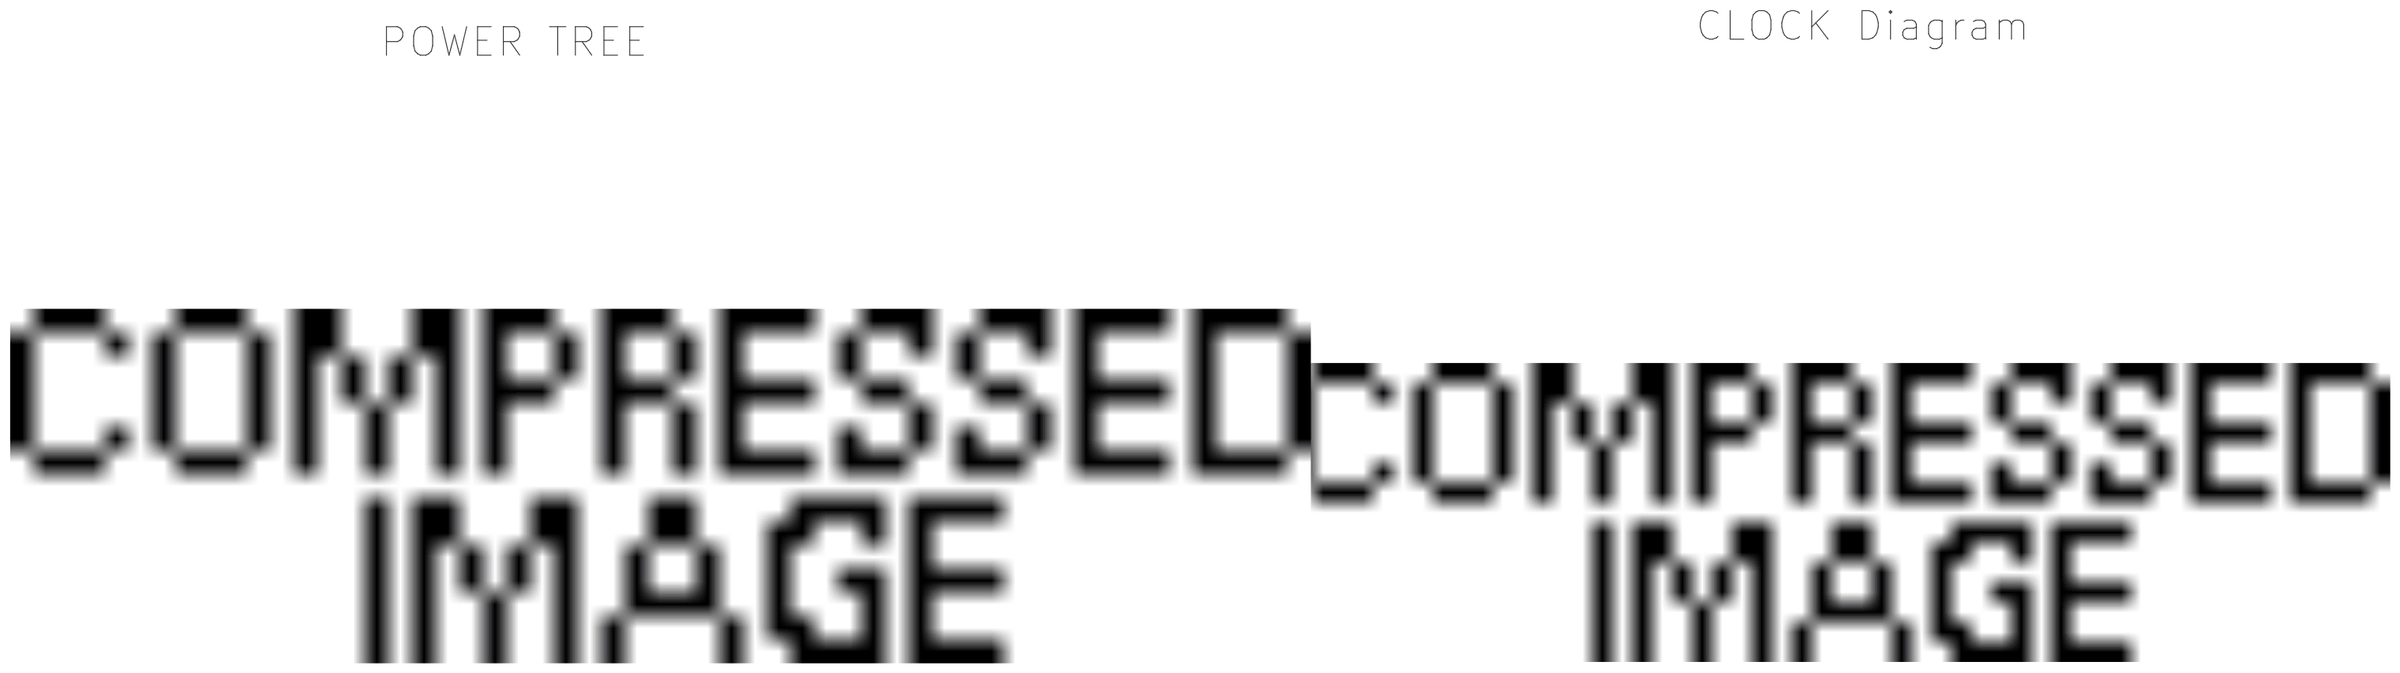
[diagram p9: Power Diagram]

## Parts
sheet Connector
C98  10uF  [C0402-L]
C99  10uF  [C0402-L]
C100  0.1uF  [C0201-L]
C153  10uF  [C0402-L]
C154  0.1uF  [C0201-L]
J1  10164228-1001A1RLF  [10164228-1001A1RLF]
J2  10164228-1001A1RLF  [10164228-1001A1RLF]
R87  4.7K  [R0201]
R88  4.7K  [R0201]
R89  4.7K  [R0201]
R90  4.7K  [R0201]
R95  4.7K  [R0201]
R96  4.7K  [R0201]
R97  0 Ohm  [R0201-L]
TP7  Test Point  [TP_SM_32]
sheet CPNX SERDES
C56  0.22uF  [C0201-L]
C57  0.22uF  [C0201-L]
C58  0.1uF  [C0201-L]
C59  10uF  [C0402-L]
C60  0.22uF  [C0201-L]
C61  0.22uF  [C0201-L]
C62  10uF  [C0402-L]
C63  10uF  [C0402-L]
C64  0.1uF  [C0201-L]
C65  0.1uF  [C0201-L]
C66  0.1uF  [C0201-L]
C67  0.1uF  [C0201-L]
C68  0.22uF  [C0201-L]
C69  0.22uF  [C0201-L]
C70  0.22uF  [C0201-L]
C71  0.22uF  [C0201-L]
C72  0.1uF  [C0201-L]
C73  0.1uF  [C0201-L]
C74  0.1uF  [C0201-L]
C75  0.1uF  [C0201-L]
C76  0.1uF  [C0201-L]
C77  10uF  [C0402-L]
C78  0.1uF  [C0201-L]
C79  10uF  [C0402-L]
C80  0.1uF  [C0201-L]
C81  10uF  [C0402-L]
C82  0.1uF  [C0201-L]
C83  10uF  [C0402-L]
C84  0.1uF  [C0201-L]
C85  10uF  [C0402-L]
C86  0.1uF  [C0201-L]
C87  10uF  [C0402-L]
C88  0.1uF  [C0201-L]
C89  0.1uF  [C0201-L]
C90  10uF  [C0402-L]
C91  10uF  [C0402-L]
C92  10uF  [C0402-L]
C93  1uF  [C0201-L]
C94  10uF  [C0402-L]
C95  1uF  [C0201-L]
C96  1uF  [C0201-L]
C97  1uF  [C0201-L]
C146  1uF  [C0201-L]
FB3  BBUP00100505221Y00  [0402]
FB4  BBUP00100505221Y00  [0402]
FB5  BBUP00100505221Y00  [0402]
FB6  BBUP00100505221Y00  [0402]
FB7  BBUP00100505221Y00  [0402]
FB8  BBUP00100505221Y00  [0402]
R32  976 Ohm  [R0201-L]
R33  976 Ohm  [R0201-L]
R34  976 Ohm  [R0201-L]
R35  100Ohm  [R0201-L]
R36  976 Ohm  [R0201-L]
R37  100Ohm  [R0201-L]
R39  10K  [R0201-L]
R40  15K  [R0201-L]
R41  20.5K  [R0201-L]
R42  20K  [R0201-L]
R43  10K  [R0201-L]
R67  10K  [R0201-L]
R76  10K  [R0201-L]
R85  49.9 Ohm  [R0201]
R86  49.9 Ohm  [R0201]
TP8  Test Point  [TP_SM_32]
TP9  Test Point  [TP_SM_32]
U10  RP120Z001D-E2-F  [6-XFBGA]
U11  RP120Z001D-E2-F  [6-XFBGA]
X3  DSC1224CI2-100M0000  [VDFN6_DSC1224CI2]
sheet CPNX_Bank-4 ,5 ,6
C42  10uF  [C0402-L]
C43  0.1uF  [C0201-L]
C44  0.1uF  [C0201-L]
C47  10uF  [C0402-L]
C48  0.1uF  [C0201-L]
C49  0.1uF  [C0201-L]
C50  0.1uF  [C0201-L]
C51  10uF  [C0402-L]
C52  0.1uF  [C0201-L]
C53  10uF  [C0402-L]
C54  1uF  [C0201-L]
C55  1uF  [C0201-L]
C148  10uF  [C0402-L]
C149  0.1uF  [C0201-L]
FB13  PBY160808T-601Y-N  [FB0603]
R28  4.7K  [R0201]
R29  4.7K  [R0201]
R30  20K  [R0201-L]
R31  20K  [R0201-L]
R68  2.2K  [R0201-L]
R80  10K  [R0201-L]
R81  33 Ohm  [R0201]
TP10  Test Point  [TP_SM_32]
U8  S27KS0642GABHV020  [24-VBGA]
U9  RP120Z001D-E2-F  [6-XFBGA]
X4  ASDAIG3-27.000MHZ-X-K-S-T  [4-SMD_2p5x2_27MHz]
sheet CPNX_Bank_0,1,2
C31  10uF  [C0402-L]
C32  0.1uF  [C0201-L]
C33  0.1uF  [C0201-L]
C34  10uF  [C0402-L]
C35  0.1uF  [C0201-L]
C36  0.1uF  [C0201-L]
C37  0.1uF  [C0201-L]
C38  10uF  [C0402-L]
C39  10uF  [C0402-L]
C45  10uF  [C0402-L]
C46  0.1uF  [C0201-L]
FB1  PBY160808T-601Y-N  [FB0603]
FB2  7427927311  [0402]
R18  4.7K  [R0201]
R22  4.7K  [R0201]
R23  4.7K  [R0201]
R24  4.7K  [R0201]
R25  2.2K  [R0201-L]
R27  10K  [R0201-L]
R69  4.7K  [R0201]
R70  1K  [R0201-L]
R71  4.7K  [R0201]
R82  33 Ohm  [R0201]
R93  4.7K  [R0201]
R94  4.7K  [R0201]
TP11  Test Point  [TP_SM_32]
TP12  Test Point  [TP_SM_32]
TP13  Test Point  [TP_SM_32]
TP14  Test Point  [TP_SM_32]
TP20  Test Point  [TP_SM_32]
U6  TMP118A  [4-XFBGA]
U7  TMP118B  [4-XFBGA]
X1  HX21C5006Z_125.00MHz  [4-SMD]
sheet CPNX_Bank_0
C1  0.1uF  [C0201-L]
C2  10uF  [C0402-L]
C3  0.1uF  [C0201-L]
C4  10uF  [C0402-L]
C11  10uF  [C0402-L]
C12  0.1uF  [C0201-L]
C13  0.1uF  [C0201-L]
C21  0.1uF  [C0201-L]
C22  0.1uF  [C0201-L]
C23  0.1uF  [C0201-L]
C24  10uF  [C0402-L]
C25  10uF  [C0402-L]
C30  0.1uF  [C0201-L]
D1  Green  [0201]
Q1  NTNS3193NZT5G  [3-XFLGA]
R1  330  [R0201-L]
R2  4.7K  [R0201]
R3  4.7K  [R0201]
R4  4.7K  [R0201]
R5  4.7K  [R0201]
R6  4.7K  [R0201]
R7  4.7K  [R0201]
R9  33 Ohm  [R0201]
R14  10K  [R0201-L]
R15  10K  [R0201-L]
U3  W25Q512JVEIM  [8-WSON_8x6]
U4  S27KS0642GABHV020  [24-VBGA]
sheet Power Supply
C117  22uF  [C0603-L]
C118  10uF  [C0402-L]
C119  22uF  [C0603-L]
C120  10uF  [C0402-L]
C121  120pF  [C0201-L]
C122  10uF  [C0402-L]
C123  22uF  [C0603-L]
C124  120pF  [C0201-L]
C125  120pF  [C0201-L]
C126  0.1uF  [C0201-L]
C127  0.1uF  [C0201-L]
C128  0.1uF  [C0201-L]
C129  10uF  [C0402-L]
C132  0.1uF  [C0201-L]
C133  10uF  [C0402-L]
C135  0.1uF  [C0201-L]
C136  0.1uF  [C0201-L]
C138  0.1uF  [C0201-L]
C139  10uF  [C0402-L]
C140  0.1uF  [C0201-L]
C141  10uF  [C0402-L]
C142  0.1uF  [C0201-L]
C143  0.1uF  [C0201-L]
C144  0.1uF  [C0201-L]
C145  10uF  [C0402-L]
C152  0.1uF  [C0201-L]
D5  Green  [0201]
FB10  7427927311  [0402]
FB11  7427927311  [0402]
FB12  7427927311  [0402]
R56  510 Ohm  [R0201-L]
R57  200K  [R0201-L]
R58  66.5K  [R0201-L]
R59  453K  [R0201-L]
R60  100K  [R0201-L]
R61  100K  [R0201-L]
R62  100K  [R0201-L]
R63  100K  [R0201-L]
R64  100K  [R0201-L]
TP1  Test Point  [TP_SM_32]
TP2  Test Point  [TP_SM_32]
TP3  Test Point  [TP_SM_32]
U1  LFCPNX-100-ASG256  [LFCPNX-100-ASG256]  (sections A,B,C,D,E,F,G,H,I,J,K,L)
U15  TPSM82822SILR  [10-uSIP_2p5x2]
U16  TPSM82822SILR  [10-uSIP_2p5x2]
U17  TPSM82822SILR  [10-uSIP_2p5x2]
sheet XO3D FPGA
C101  10uF  [C0402-L]
C102  0.1uF  [C0201-L]
C103  0.1uF  [C0201-L]
C104  1.0uF  [C0402-L]
C105  1.0uF  [C0402-L]
C106  0.1uF  [C0201-L]
C107  0.1uF  [C0201-L]
C108  10uF  [C0402-L]
C109  10uF  [C0402-L]
C110  0.1uF  [C0201-L]
C111  0.1uF  [C0201-L]
C112  10uF  [C0402-L]
C113  10uF  [C0402-L]
C114  1.0uF  [C0402-L]
C115  1.0uF  [C0402-L]
C116  0.1uF  [C0201-L]
C150  10uF  [C0402-L]
C151  0.1uF  [C0201-L]
D3  Green  [0201]
FB14  PBY160808T-601Y-N  [FB0603]
Q2  NTNS3193NZT5G  [3-XFLGA]
R44  200K  [R0201-L]
R45  4.7K  [R0201]
R46  33 Ohm  [R0201]
R47  200K  [R0201-L]
R48  330  [R0201-L]
R49  4.7K  [R0201]
R50  2.2K  [R0201-L]
R51  4.7K  [R0201]
R52  4.7K  [R0201]
R55  4.7K  [R0201]
R72  1K  [R0201-L]
R73  4.7K  [R0201]
R74  0 Ohm  [R0201-L]
R75  0 Ohm  [R0201-L]
R77  4.7K  [R0201]
R83  10K  [R0201-L]
R84  33 Ohm  [R0201]
TP5  Test Point  [TP_SM_32]
TP6  Test Point  [TP_SM_32]
TP15  Test Point  [TP_SM_32]
TP16  Test Point  [TP_SM_32]
TP17  Test Point  [TP_SM_32]
TP18  Test Point  [TP_SM_32]
TP19  Test Point  [TP_SM_32]
U12  LCMXO3D-9400-UWG69  [LCMXO3D-9400-UWG69]
U13  TPS7A2033PYCJR  [4-DSBGA]
U14  TPS7A2012PYCJR  [4-DSBGA]
X5  ASDAIG-24.000MHZ-X-K-S-T  [4-SMD_2p5x2_24MHz]

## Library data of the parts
C2 C4 C11 C24 C25 C31 C34 C38 C39 C42 C45 C47 C51 C53 C59 C62 C63 C77 C79 C81 C83 C85 C87 C90-C92 C94 C98 C99 C101 C108 C109 C112 C113 C118 C120 C122 C129 C133 C139 C141 C145 C148 C150 C153 = CAP_NP: CAP CER 10UF 10V X5R 0402; Manufacturer: Yageo; Manufacturer Part Number: CC0402MRX5R6BB106; Part Number: CC0402MRX5R6BB106; Part type: Ceramic; Tolerance: 20%; Voltage: 10V; Datasheet: https://www.yageo.com/upload/media/product/app/datasheet/mlcc/upy-gphc_x5r_4v-to-50v.pdf
C1 C3 C12 C13 C21-C23 C30 C32 C33 C35-C37 C43 C44 C46 C48-C50 C52 C58 C64-C67 C72-C76 C78 C80 C82 C84 C86 C88 C89 C100 C102 C103 C106 C107 C110 C111 C116 C126-C128 C132 C135 C136 C138 C140 C142-C144 C149 C151 C152 C154 = CAP_NP: 0.1 µF ±10% 10V Ceramic Capacitor X5R 0201 (0603 Metric); Manufacturer: TDK; Manufacturer Part Number: C0603X5R1A104K030BC; Part Number: C0603X5R1A104K030BC; Part type: Ceramic; Tolerance: 10%; Voltage: 10V; Datasheet: https://product.tdk.com/system/files/dam/doc/product/capacitor/ceramic/mlcc/catalog/mlcc_commercial_general_en.pdf
J1 J2 = 10164227-1004A1RLF_8: 100 Position Connector Header, Outer Shroud Contacts Surface Mount Gold; Manufacturer: Amphenol ICC (FCI); Part Type: Connector; Datasheet: https://cdn.amphenol-cs.com/media/wysiwyg/files/documentation/datasheet/boardwiretoboard/bwb_bergstak_0_40mm_btb.pdf
R71 R73 R87 R88 R95 = R: RES SMD 4.7K OHM 1% 1/20W 0201; Assy: DNL; Manufacturer: ERJ-1GNF4701C; Manufacturer Part Number: ERJ-1GNF4701C; Part Number: ERJ-1GNF4701C; Part type: Thick Film; Power: 1/20W; Tolerance: 1%; Datasheet: https://industrial.panasonic.com/cdbs/www-data/pdf/RDA0000/AOA0000C304.pdf
R2-R7 R18 R22-R24 R28 R29 R45 R49 R51 R52 R55 R69 R77 R89 R90 R93 R94 R96 = R: RES SMD 4.7K OHM 1% 1/20W 0201; Manufacturer: ERJ-1GNF4701C; Manufacturer Part Number: ERJ-1GNF4701C; Part Number: ERJ-1GNF4701C; Part type: Thick Film; Power: 1/20W; Tolerance: 1%; Datasheet: https://industrial.panasonic.com/cdbs/www-data/pdf/RDA0000/AOA0000C304.pdf
R74 R97 = R: RES SMD 0 OHM JUMPER 1/20W 0201; Manufacturer: Vishay Dale; Manufacturer Part Number: CRCW02010000Z0ED; Part Number: CRCW02010000Z0ED; Part type: Thick Film; Power: 1/20W; Tolerance: 1%; Datasheet: https://www.vishay.com/docs/20052/crcw0201e3.pdf
TP1-TP3 TP5-TP20 = TP1: Test point 0.32" surface mount; Manufacturer: NA; Manufacturer Part Number: TP_SM; Part Number: TP_SM; Datasheet: NA
C56 C57 C60 C61 C68-C71 = CAP_NP: CAP CER 0.22UF 10V X5R 0201; Manufacturer: Murata Electronics; Manufacturer Part Number: GRM033R61A224KE90D; Part Number: GRM033R61A224KE90D; Part type: Ceramic; Tolerance: 10%; Voltage: 10V; Datasheet: https://search.murata.co.jp/Ceramy/image/img/A01X/G101/ENG/GRM033R61A224KE90-01.pdf
C54 C55 C93 C95-C97 C146 = CAP_NP: 1 µF ±20% 10V Ceramic Capacitor X5R 0201 (0603 Metric); Manufacturer: Murata Electronics; Manufacturer Part Number: GRM033R61A105ME15D; Part Number: GRM033R61A105ME15D; Part type: Ceramic; Tolerance: 20%; Voltage: 10V; Datasheet: https://search.murata.co.jp/Ceramy/image/img/A01X/G101/ENG/GRM033R61A105ME15-01.pdf
FB3-FB8 = FB_Inductor: Ferrite Beads 1.4 A 25 % IMP=220 Ohms Shielded SMD/SMT DCR=100 mOhms - 55 C to + 125 C; Current: 1.4A; DCR: 100mOhm; Manufacturer: Pulse Electronics; Datasheet: https://www.mouser.in/datasheet/2/447/EMI-3217982.pdf
R32-R34 R36 = R: RES SMD 976 OHM 0.1% 1/20W 0201; Manufacturer: Panasonic Electronic Components; Manufacturer Part Number: ERA-1ARB9760C; Part Number: ERA-1ARB9760C; Part type: Thick Film; Power: 1/20W; Tolerance: 0.1%; Datasheet: https://mm.digikey.com/Volume0/opasdata/d220001/medias/docus/2414/ERA%201A%2C2A%2C3A%2C6A%2C8A.pdf
R35 R37 = R: RES 100 OHM 1% 1/20W 0201; Manufacturer: Yageo; Manufacturer Part Number: RC0201FR-07100RL; Part Number: RC0201FR-07100RL; Part type: Thick Film; Power: 1/20W; Tolerance: 1%; Datasheet: https://www.yageo.com/upload/media/product/products/datasheet/rchip/PYu-RC_Group_51_RoHS_L_12.pdf
R14 R15 R27 R39 R43 R76 R80 R83 = R: RES 10K OHM 1% 1/20W 0201; Manufacturer: YAGEO; Manufacturer Part Number: RC0201FR-0710KL; Part Number: RC0201FR-0710KL; Part type: Thick Film; Power: 1/20W; Tolerance: 1%; Datasheet: https://www.yageo.com/upload/media/product/products/datasheet/rchip/PYu-RC_Group_51_RoHS_L_12.pdf
R40 = R: RES SMD 15K OHM 1% 1/20W 0201; Manufacturer: ERJ-1GNF1502C; Manufacturer Part Number: ERJ-1GNF1502C; Part Number: ERJ-1GNF1502C; Part type: Thick Film; Power: 1/20W; Tolerance: 1%; Datasheet: https://industrial.panasonic.com/cdbs/www-data/pdf/RDA0000/AOA0000C304.pdf
R41 = R: RES 20.5K OHM 1% 1/20W 0201; Manufacturer: Yageo; Manufacturer Part Number: RC0201FR-0720K5L; Part Number: RC0201FR-0720K5L; Part type: Thick film; Power: 1/20W; Tolerance: 1%; Datasheet: https://www.yageo.com/upload/media/product/products/datasheet/rchip/PYu-RC_Group_51_RoHS_L_12.pdf
R30 R31 R42 = R: RES 20K OHM 1% 1/20W 0201; Manufacturer: YAGEO; Manufacturer Part Number: RC0201FR-0720KL; Part Number: RC0201FR-0720KL; Part type: Thick Film; Power: 1/20W; Tolerance: 1%; Datasheet: https://www.yageo.com/upload/media/product/products/datasheet/rchip/PYu-RC_Group_51_RoHS_L_12.pdf
R67 = R: RES 10K OHM 1% 1/20W 0201; Assy: DNL; Manufacturer: YAGEO; Manufacturer Part Number: RC0201FR-0710KL; Part Number: RC0201FR-0710KL; Part type: Thick Film; Power: 1/20W; Tolerance: 1%; Datasheet: https://www.yageo.com/upload/media/product/products/datasheet/rchip/PYu-RC_Group_51_RoHS_L_12.pdf
R85 R86 = R: RES 49.9 OHM 0.5% 1/20W 0201; Manufacturer: Yageo; Manufacturer Part Number: RC0201DR-0749R9L; Part Number: RC0201DR-0749R9L; Part type: Thick Film; Power: 1/20W; Tolerance: 0.5%; Datasheet: https://www.yageo.com/upload/media/product/products/datasheet/rchip/PYu-RC_Group_51_RoHS_L_12.pdf
U9-U11 = RP120Z001D-E2-F: Linear Voltage Regulator IC Positive Adjustable 1 Output 1.5A WLCSP-6-P11; FPLIST: 6-XFBGA, WLCSP; Manufacturer: Nisshinbo Micro Devices Inc.; Part Type: Regulator; Datasheet: https://www.nisshinbo-microdevices.co.jp/en/pdf/datasheet/rp120-ea.pdf
X3 = DSC1224CI2: Standard Clock Oscillators MEMS OSC, HCSL, 100MHz, 25PPM, 2.5-3.3V, -40 to 85C, 3.2 x 2.5mm; Manufacturer: Microchip; Part Type: Oscillator; Datasheet: https://www.mouser.in/datasheet/2/268/DSC12x2_3_4_High_Performance_Differential_MEMS_Osc-3314884.pdf
FB1 FB13 FB14 = FB_Inductor: FERRITE BEAD BEAD_0603 Ferrite 600ohm 25% 200mohm 0.8A; Current: 0.8A; DCR: 200mohm; Manufacturer: Yageo Corporation
R25 R50 R68 = R: RES 2.2K OHM 1% 1/20W 0201; Manufacturer: YAGEO; Manufacturer Part Number: RC0201FR-072K2L; Part Number: RC0201FR-072K2L; Part type: Thick Film; Power: 1/20W; Tolerance: 1%; Datasheet: https://www.yageo.com/upload/media/product/products/datasheet/rchip/PYu-RC_Group_51_RoHS_L_12.pdf
R9 R46 R81 R82 R84 = R: RES 33 OHM 1% 1/20W 0201; Manufacturer: Yageo; Manufacturer Part Number: RC0201FR-0733RL; Part Number: RC0201FR-0733RL; Part type: Thick Film; Power: 1/20W; Tolerance: 1%; Datasheet: https://www.yageo.com/upload/media/product/products/datasheet/rchip/PYu-RC_Group_51_RoHS_L_12.pdf
U4 U8 = S27KS0642GABHV020: PSRAM (Pseudo SRAM) Memory IC 64Mbit HyperBus 200 MHz 35 ns 24-FBGA (6x8); Manufacturer: Infineon Technologies; Part Type: Memory; Datasheet: https://www.infineon.com/dgdl/Infineon-S27KL0642_S27KS0642_3.0_V_1.8_V_64_Mb_(8_MB)_HyperRAM_Self-Refresh_DRAM-DataSheet-v09_00-EN.pdf?fileId=8ac78c8c7d0d8da4017d0ee8a1c47164
X4 = ASE3-27.000MHz-K-T: 27 MHz XO (Standard) CMOS Oscillator 1.8V Enable/Disable 4-SMD, No Lead; Manufacturer: Abracon LLC; Part Type: Oscillator; Datasheet: https://abracon.com/Oscillators/ASE3series.pdf
FB2 FB10-FB12 = FB_Inductor: 120 Ohms @ 100 MHz 1 Signal Line Ferrite Bead 0402 (1005 Metric) 1.2A 90mOhm; Current: 1.2A; DCR: 90mOhm; Manufacturer: Würth Elektronik; Datasheet: https://www.we-online.com/components/products/datasheet/7427927311.pdf
R70 R72 = R: RES SMD 1K OHM 1% 1/20W 0201; Manufacturer: Vishay Dale; Manufacturer Part Number: CRCW02011K00FKED; Part Number: CRCW02011K00FKED; Part type: Thick Film; Power: 1/20W; Tolerance: 1%; Datasheet: https://www.vishay.com/docs/20052/crcw0201e3.pdf
U6 = TMP118MAIYMSR: 0.1C ACCURATE DIGITAL TEMPERATUR; Manufacturer: Texas Instruments; Part Type: SENSOR; Datasheet: https://www.ti.com/lit/ds/symlink/tmp118.pdf?ts=1742898628311&ref_url=https%253A%252F%252Fwww.ti.com%252Fproduct%252FTMP118
U7 = TMP118MAIYMSR: 0.1C ACCURATE DIGITAL TEMPERATUR; Manufacturer: Texas Instruments; Manufacturer Part Number: TMP118MBIYMSR; Part Number: TMP118MBIYMSR; Part Type: SENSOR; Datasheet: https://www.ti.com/lit/ds/symlink/tmp118.pdf?ts=1742898628311&ref_url=https%253A%252F%252Fwww.ti.com%252Fproduct%252FTMP118
X1 = X-DIODES_125MHz_3.3V: Manufacturer: Diodes Incorporated; Manufacturer Part Number: HX21C5006Z
D1 D3 D5 = LED_0: Green 571nm LED Indication - Discrete 1.97V 2-SMD, 0201; Current: 10mA; Manufacturer: Kingbright; Manufacturer Part Number: APG0603CGC-TT; Part Number: APG0603CGC-TT; Part type: LED; Voltage: 1.97; Datasheet: https://www.kingbrightusa.com/images/catalog/SPEC/APG0603CGC-TT.pdf
Q1 Q2 = N-MOS: MOSFET N-CH 20V 224MA 3XLLGA; Manufacturer: onsemi; Part Type: MOSFET N-CH; Datasheet: https://www.onsemi.com/pdf/datasheet/ntns3193nz-d.pdf
R1 R48 = R: RES SMD 330 OHM 1% 1/20W 0201; Manufacturer: YAGEO; Manufacturer Part Number: AC0201FR-07330RL; Part Number: AC0201FR-07330RL; Part type: Thick Film; Power: 1/20W; Tolerance: 1%; Datasheet: https://www.yageo.com/upload/media/product/productsearch/datasheet/rchip/PYu-AC_51_RoHS_L_11.pdf
U3 = W25Q512JVEIM: FLASH - NOR Memory IC 512Mbit SPI - Quad I/O 133 MHz 8-WSON (8x6); Manufacturer: Winbond Electronics; Part Type: FLASH; Datasheet: https://www.winbond.com/resource-files/W25Q512JV%20DTR%20RevD%2006292020%20133.pdf
C117 C119 C123 = CAP_NP: 22 µF ±20% 10V Ceramic Capacitor X5R 0603 (1608 Metric); Manufacturer: Murata; Manufacturer Part Number: GRM188R61A226ME15D; Part Number: GRM188R61A226ME15D; Part type: Ceramic; Tolerance: 20%; Voltage: 10V; Datasheet: https://search.murata.co.jp/Ceramy/image/img/A01X/G101/ENG/GRM188R61A226ME15-01.pdf
C121 C124 C125 = CAP_NP: CAP CER 120PF 50V C0G/NP0 0201; Manufacturer: Murata Electronics; Manufacturer Part Number: GRM0335C1H121JA01D; Part Number: GRM0335C1H121JA01D; Part type: Ceramic; Tolerance: 5%; Voltage: 50V; Datasheet: https://search.murata.co.jp/Ceramy/image/img/A01X/G101/ENG/GRM0335C1H121JA01-01.pdf
R56 = R: RES SMD 510 OHM 1% 1/20W 0201; Manufacturer: Vishay Dale; Manufacturer Part Number: CRCW0201510RFNED; Part Number: CRCW0201510RFNED; Part type: Thick Film; Power: 1/20W; Tolerance: 1%; Datasheet: https://www.vishay.com/docs/20052/crcw0201e3.pdf
R44 R47 R57 = R: RES SMD 200K OHM 1% 1/20W 0201; Manufacturer: Panasonic Electronic Components; Manufacturer Part Number: ERJ-1GNF2003C; Part Number: ERJ-1GNF2003C; Part type: Thick Film; Power: 1/20W; Tolerance: 1%; Datasheet: https://industrial.panasonic.com/cdbs/www-data/pdf/RDA0000/AOA0000C304.pdf
R58 = R: RES SMD 66.5K OHM 1% 1/20W 0201; Manufacturer: Panasonic Electronic Components; Manufacturer Part Number: ERJ-1GNF6652C; Part Number: ERJ-1GNF6652C; Part type: Thick Film; Power: 1/20W; Tolerance: 1%; Datasheet: https://industrial.panasonic.com/cdbs/www-data/pdf/RDA0000/AOA0000C304.pdf
R59 = R: RES SMD 453K OHM 1% 1/20W 0201; Manufacturer: Panasonic Electronic Components; Manufacturer Part Number: ERJ-1GNF4533C; Part Number: ERJ-1GNF4533C; Part type: Thick Film; Power: 1/22W; Tolerance: 1%; Datasheet: https://industrial.panasonic.com/cdbs/www-data/pdf/RDA0000/AOA0000C304.pdf
R60-R64 = R: RES SMD 100K OHM 1% 1/20W 0201; Manufacturer: Panasonic Electronic Components; Manufacturer Part Number: ERJ-1GNF1003C; Part Number: ERJ-1GNF1003C; Part type: Thick Film; Power: 1/20W; Tolerance: 1%; Datasheet: https://industrial.panasonic.com/cdbs/www-data/pdf/RDA0000/AOA0000C304.pdf
U1 = LFCPNX-100-ASG256
U15-U17 = TPSM82822SILR: Non-Isolated PoL Module DC DC Converter 1 Output 0.6 ~ 4V 2A 2.4V - 5.5V Input; Manufacturer: Texas Instruments; Part Type: Regulator; Datasheet: https://www.ti.com/lit/ds/symlink/tpsm82821.pdf?HQS=dis-dk-null-digikeymode-dsf-pf-null-wwe&ts=1741858078546
C104 C105 C114 C115 = CAP_NP: 1 µF ±10% 25V Ceramic Capacitor X5R 0402 (1005 Metric); Manufacturer: Murata; Manufacturer Part Number: GRM155R61E105KA12D; Part Number: GRM155R61E105KA12D; Part type: Ceramic; Tolerance: 10%; Voltage: 25V; Datasheet: https://www.digikey.com/en/htmldatasheets/production/2354729/0/0/1/grm155r61e105ka12x-ref-sheet.html?site=US&lang=en&cur=USD
R75 = R: RES SMD 0 OHM JUMPER 1/20W 0201; Assy: DNL; Manufacturer: Vishay Dale; Manufacturer Part Number: CRCW02010000Z0ED; Part Number: CRCW02010000Z0ED; Part type: Thick Film; Power: 1/20W; Tolerance: 1%; Datasheet: https://www.vishay.com/docs/20052/crcw0201e3.pdf
U12 = LCMXO3D-9400-UWG69_0
U13 = TPS7A20: IC REG LINEAR 3.3V 300MA 4-DSBGA; Manufacturer: Texas Instruments; Part Type: Regulator; Datasheet: https://www.ti.com/lit/ds/symlink/tps7a20.pdf?ts=1742328504184&ref_url=https%253A%252F%252Fwww.ti.com%252Fproduct%252FTPS7A20%252Fpart-details%252FTPS7A2033PDQNR
U14 = TPS7A20: IC REG LINEAR 1.2V 300MA 4-DSBGA; Manufacturer: Texas Instruments; Part Type: Regulator; Datasheet: https://www.ti.com/lit/ds/symlink/tps7a20.pdf?ts=1742328504184&ref_url=https%253A%252F%252Fwww.ti.com%252Fproduct%252FTPS7A20%252Fpart-details%252FTPS7A2033PDQNR
X5 = ASE3-27.000MHz-K-T: 24 MHz XO (Standard) CMOS Oscillator 3.3V Enable/Disable 4-SMD, No Lead; Manufacturer: Abracon LLC; Part Type: Oscillator; Datasheet: https://abracon.com/Oscillators/ASEseries.pdf

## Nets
GND: C1.2 C2.2 C3.2 C4.2 C11.2 C12.2 C13.2 C21.2 C22.2 C23.2 C24.2 C25.2 C30.2 C31.2 C32.2 C33.2 C34.2 C35.2 C36.2 C37.2 C38.2 C39.2 C42.2 C43.2 C44.2 C45.2 C46.2 C47.2 C48.2 C49.2 C50.2 C51.2 C52.2 C53.2 C54.2 C55.2 C58.2 C59.2 C62.2 C63.2 C64.2 C65.2 C66.2 C67.2 C92.2 C93.2 C94.2 C95.2 C96.2 C97.2 C98.2 C99.2 C100.2 C101.2 C102.2 C103.2 C104.2 C105.2 C106.2 C107.2 C108.2 C109.2 C110.2 C111.2 C112.2 C113.2 C114.2 C115.2 C116.2 C117.2 C118.2 C119.2 C120.2 C122.2 C123.2 C126.2 C127.2 C128.2 C129.2 C132.2 C133.2 C135.2 C136.2 C138.2 C139.2 C140.2 C141.2 C142.2 C143.2 C144.2 C145.2 C146.2 C148.2 C149.2 C150.2 C151.2 C152.2 C153.2 C154.2 D5.K(CATHODE) J1.2 J1.8 J1.14 J1.17 J1.27 J1.28 J1.37 J1.38 J1.41 J1.47 J1.48 J1.57 J1.58 J1.67 J1.68 J1.79 J1.80 J1.87 J1.88 J1.99 J1.100 J1.S1 J1.S2 J1.S3 J1.S4 J2.1 J2.2 J2.7 J2.8 J2.13 J2.14 J2.19 J2.20 J2.25 J2.26 J2.31 J2.32 J2.37 J2.38 J2.43 J2.44 J2.49 J2.50 J2.55 J2.56 J2.61 J2.62 J2.67 J2.68 J2.73 J2.74 J2.79 J2.80 J2.85 J2.86 J2.91 J2.92 J2.99 J2.100 J2.S1 J2.S2 J2.S3 J2.S4 Q1.2(SOURCE) Q2.2(SOURCE) R25.2 R31.2 R42.2 R43.2 R50.2 R61.2 R62.2 R64.2 R67.1 R71.2 R73.2 R85.2 R86.2 R89.2 R90.2 R96.2 TP19.1(TP) TP20.1(TP) U1.A1(VSSSDQ) U1.A3(VSSSDQ) U1.A16(VSSSDQ) U1.B4(VSSSDQ) U1.B5(VSSSDQ) U1.B9(VSSSDQ) U1.B14(VSSSDQ) U1.C7(VSSSDQ) U1.C10(VSSSDQ) U1.C12(VSSSDQ) U1.D12(VSS) U1.D14(VSSSDQ) U1.E9(VSSSDQ) U1.E11(VSSSDQ) U1.F4(VSS) U1.G8(VSS) U1.G13(VSS) U1.J4(VSS) U1.J13(VSS) U1.L1(ADC_DP0) U1.L2(ADC_REFP0) U1.M1(ADC_DN0) U1.M2(ADC_REFP1) U1.N1(VSSADC) U1.N2(ADC_DP1) U1.N8(VSS) U1.N11(VSS) U1.N13(VSS) U1.P2(ADC_DN1) U1.P4(VSS) U1.P6(VSS) U1.T1(VSS) U1.T16(VSS) U3.4(GND) U3.9(EP) U4.B3(VSS) U4.C1(VSSQ_1) U4.E5(VSSQ_2) U6.A2(GND) U7.A2(GND) U8.B3(VSS) U8.C1(VSSQ_1) U8.E5(VSSQ_2) U9.C1(GND) U10.C1(GND) U11.C1(GND) U12.A4(GND) U12.C8(GND) U12.E3(GND) U12.E5(GND) U13.B2(GND) U14.B2(GND) U15.9(GND) U15.10(GND) U16.9(GND) U16.10(GND) U17.9(GND) U17.10(GND) X1.2(GND) X3.3(GND) X4.2(GND) X5.2(GND)
VCC_1V0: C119.1 C121.1 C126.1 C127.1 C128.1 C129.1 C132.1 C133.1 C135.1 C136.1 R58.1 TP2.1(TP) U1.F8(VCC) U1.H13(VCC) U1.J3(VCC) U1.M8(VCC) U1.N10(VCCECLK) U1.P7(VCCECLK) U16.5(VOUT) U16.6(VOUT) U16.7(VOUT)
VCC_1V0_LDO: C62.1 C63.1 C64.1 C65.1 C66.1 C67.1 C92.1 FB3.1 R40.1 TP8.1(TP) U1.A7(VCCSD3) U1.A10(VCCSD2) U1.A13(VCCSD1) U1.B16(VCCSD0) U10.A1(VOUT)
VCC_1V2_LDO: C101.1 C102.1 C103.1 C115.1 R44.2 TP5.1(TP) U12.B8(VCC) U12.E4(VCC) U14.A2(OUT)
VCC_1V2_LDO_MIPI: C51.1 C52.1 C53.1 R30.1 TP10.1(TP) U1.M9(VCCIO4) U1.P8(VCCIO4) U9.A1(VOUT)
VCC_1V8: C11.1 C12.1 C13.1 C21.1 C22.1 C23.1 C24.1 C25.1 C30.1 C32.1 C34.1 C42.1 C43.1 C44.1 C47.1 C48.1 C49.1 C50.1 C54.1 C93.1 C117.1 C124.1 FB2.2 FB10.2 FB11.2 FB12.2 FB13.1 R14.1 R15.1 R28.1 R29.1 R57.2 R68.1 R87.1 R88.1 R95.1 TP1.1(TP) U1.F13(VCCIO7) U1.N14(VCCIO5) U1.P3(VCCIO3) U1.P5(VCCIO3) U1.T15(VCCIO5) U4.B4(VCC) U4.D1(VCCQ_2) U4.E4(VCCQ_1) U8.B4(VCC) U8.D1(VCCQ_2) U8.E4(VCCQ_1) U9.A2(VIN) U10.A2(VIN) U15.5(VOUT) U15.6(VOUT) U15.7(VOUT)
VCC_1V8_LDO: C94.1 FB4.1 FB5.1 FB6.1 FB7.1 FB8.1 R41.1 TP9.1(TP) U11.A1(VOUT)
VCC_3V3: C3.1 C4.1 C31.1 C33.1 C35.1 C36.1 C37.1 C38.1 C95.1 C123.1 C125.1 C146.1 FB1.2 R1.2 R5.1 R6.1 R7.1 R18.1 R22.1 R23.1 R24.1 R39.1 R59.1 R69.1 R70.1 R76.1 R97.2 TP3.1(TP) U1.E4(VCCIO0) U1.G4(VCCIO1) U1.J5(VCCIO2) U6.A1(VDD) U7.A1(VDD) U11.A2(VIN) U17.5(VOUT) U17.6(VOUT) U17.7(VOUT) X3.6(VDD)
VCC_3V3_LDO: C1.1 C2.1 C105.1 C107.1 C108.1 C109.1 C110.1 C111.1 C112.1 C113.1 C116.1 FB14.1 R2.1 R3.1 R4.1 R45.1 R48.2 R49.1 R51.1 R52.1 R55.1 R60.1 R63.2 R72.1 R77.2 TP6.1(TP) U3.8(VCC) U12.B4(VCCIO0) U12.D3(VCCIO1) U12.D8(VCCIO3) U12.F4(VCCIO2) U13.A2(OUT)
VCC_5V0: C55.1 C96.1 C97.1 C98.1 C99.1 C100.1 C104.1 C114.1 C118.1 C120.1 C122.1 J1.1 J1.3 J1.5 J1.7 J1.9 J1.11 R47.2 R56.1 TP7.1(TP) U9.C2(VBIAS) U10.C2(VBIAS) U11.C2(VBIAS) U13.A1(IN) U14.A1(IN) U15.1(VIN) U15.2(VIN) U16.1(VIN) U16.2(VIN) U17.1(VIN) U17.2(VIN)
VCC_CAM: C45.1 C46.1 C153.1 C154.1 J1.13 J1.15 R93.1 R94.1 R97.1 U1.J14(VCCIO6)
VCCAUX: C138.1 C139.1 FB10.1 U1.H8(VCCAUX)
VCCAUXA: C140.1 C141.1 FB11.1 U1.D13(VCCAUXA)
VCCAUXH: C142.1 C143.1 C144.1 C145.1 FB12.1 U1.N9(VCCAUXH4) U1.N12(VCCAUXH5) U1.T2(VCCAUXH3)
VCCAUXSDQ0: C76.1 C77.1 C78.1 C79.1 C80.1 C81.1 C89.1 C90.1 FB4.2 U1.A4(VCCAUXSDQ0)
VCCPLLSD0: C82.1 C83.1 FB5.2 U1.B15(VCCPLLSD0)
VCCPLLSD1: C84.1 C85.1 FB6.2 U1.B11(VCCPLLSD1)
VCCPLLSD2: C86.1 C87.1 FB7.2 U1.D9(VCCPLLSD2)
VCCPLLSD3: C88.1 C91.1 FB8.2 U1.B7(VCCPLLSD3)
VCCSDCK: C58.1 C59.1 FB3.2 U1.D11(VCCSDCK)
CPNX_1V0_EN: C152.1 R60.2 U12.G4(PB32A) U16.3(EN)
CPNX_125MHz_CLK: R82.2 U1.F10(PR4A/URC_GPLL0T_IN)
CPNX_CAM0_MIPI_CKN: J2.29 U1.M6(PB106B/PCLKC4_3)
CPNX_CAM0_MIPI_CKP: J2.27 U1.M7(PB106A/PCLKT4_3)
CPNX_CAM0_MIPI_D0N: J2.5 U1.K10(PB50B)
CPNX_CAM0_MIPI_D0P: J2.3 U1.K11(PB50A/VREF4_1)
CPNX_CAM0_MIPI_D1N: J2.11 U1.K7(PB100B/PCLKC4_2/ADC_CN7)
CPNX_CAM0_MIPI_D1P: J2.9 U1.K8(PB100A/PCLKT4_2/ADC_CP7)
CPNX_CAM0_MIPI_D2N: J2.17 U1.L7(PB98B/ADC_CN5)
CPNX_CAM0_MIPI_D2P: J2.15 U1.L8(PB98A/ADC_CP5)
CPNX_CAM0_MIPI_D3N: J2.23 U1.L10(PB56B)
CPNX_CAM0_MIPI_D3P: J2.21 U1.M10(PB56A)
CPNX_CAM1_MIPI_CKN: J2.47 U1.L9(PB58B/PCLKC4_1)
CPNX_CAM1_MIPI_CKP: J2.45 U1.K9(PB58A/PCLKT4_1)
CPNX_CAM1_MIPI_D0N: J2.35 U1.P10(PB60B)
CPNX_CAM1_MIPI_D0P: J2.33 U1.P9(PB60A)
CPNX_CAM1_MIPI_D1N: J2.41 U1.R10(PB54B)
CPNX_CAM1_MIPI_D1P: J2.39 U1.T10(PB54A)
CPNX_CAM1_MIPI_D2N: J2.53 U1.T8(PB102B/ADC_CN6)
CPNX_CAM1_MIPI_D2P: J2.51 U1.R8(PB102A/ADC_CP6)
CPNX_CAM1_MIPI_D3N: J2.59 U1.N6(PB108B/VREF4_2)
CPNX_CAM1_MIPI_D3P: J2.57 U1.N7(PB108A)
CPNX_DONE: Q1.1(GATE) R5.2 U1.D5(PT136B/DONE) U12.H4(PB29A/PCLKT2_1)
CPNX_HPIO_1N: J2.65 U1.R11(PB44B)
CPNX_HPIO_1P: J2.63 U1.T11(PB44A)
CPNX_HPIO_2N: J2.71 U1.J12(PB38B)
CPNX_HPIO_2P: J2.69 U1.K12(PB38A)
CPNX_HPIO_3N: J2.77 U1.M11(PB48B/VREF5_2)
CPNX_HPIO_3P: J2.75 U1.M12(PB48A)
CPNX_HPIO_4N: J2.72 U1.R9(PB52B/PCLKC4_0)
CPNX_HPIO_4P: J2.70 U1.T9(PB52A/PCLKT4_0)
CPNX_HPIO_5N: J2.66 U1.K4(PB146B/ADC_CN14)
CPNX_HPIO_5P: J2.64 U1.L4(PB146A/ADC_CP14)
CPNX_HPIO_6N: J1.6 U1.R4(PB148B/PCLKC3_2/COMP3IN)
CPNX_HPIO_6P: J1.4 U1.T4(PB148A/PCLKT3_2/COMP3IP)
CPNX_HPIO_7N: J1.12 U1.T3(PB150B/ADC_CN11)
CPNX_HPIO_7P: J1.10 U1.R3(PB150A/ADC_CP11)
CPNX_HPIO_8N: J1.18 U1.R1(PB152B/ADC_CN12)
CPNX_HPIO_8P: J1.16 U1.R2(PB152A/ADC_CP12)
CPNX_HPIO_9N: J1.45 U1.K3(PB156B/LRC_GPLL0C_IN/VREF3_2)
CPNX_HPIO_9P: J1.43 U1.L3(PB156A/LRC_GPLL0T_IN)
CPNX_HPIO_10P: J1.39 U1.K6(PB110A/VREF3_1/ADC_CP10)
CPNX_I2C_SCL_3V3: J2.81 R69.2 U1.F2(PR11B/SCL) U6.B2(SCL) U7.B2(SCL)
CPNX_I2C_SDA_3V3: J2.83 R18.2 U1.E2(PR11A/SDA) U6.B1(SDA) U7.B1(SDA)
CPNX_INITN: R7.2 U1.E7(PT134A/INITN) U12.H5(PB22A/PCLKT2_0)
CPNX_JTAG_CLK: J1.97 R25.1 TP11.1(TP) U1.E1(PR13A/TCK/SCLK/PMU_EXT_CLK)
CPNX_JTAG_EN: J1.89 R70.2 R71.1 U1.D6(JTAG_EN)
CPNX_JTAG_TDI: J1.93 R23.2 TP13.1(TP) U1.F5(PR8B/TDI/SSI)
CPNX_JTAG_TDO: J1.91 R22.2 TP14.1(TP) U1.F3(PR10B/TDO/SSO)
CPNX_JTAG_TMS: J1.95 R24.2 TP12.1(TP) U1.G7(PR6B/TMS/SCSN)
CPNX_PROGRAMN: R6.2 R74.1 R75.1 U1.D7(PT134B/PROGRAMN)
CPNX_SD0_RXDN: J2.48 U1.C14(SD0_RXDN)
CPNX_SD0_RXDP: J2.46 U1.C13(SD0_RXDP)
CPNX_SD0_TXDN: C57.2 J2.42
CPNX_SD0_TXDP: C56.2 J2.40
CPNX_SD1_RXDN: J2.36 U1.B10(SD1_RXDN)
CPNX_SD1_RXDP: J2.34 U1.C11(SD1_RXDP)
CPNX_SD1_TXDN: C61.2 J2.30
CPNX_SD1_TXDP: C60.2 J2.28
CPNX_SD2_RXDN: J2.24 U1.C9(SD2_RXDN)
CPNX_SD2_RXDP: J2.22 U1.C8(SD2_RXDP)
CPNX_SD2_TXDN: C69.2 J2.18
CPNX_SD2_TXDP: C68.2 J2.16
CPNX_SD3_RXDN: J2.12 U1.C5(SD3_RXDN)
CPNX_SD3_RXDP: J2.10 U1.C6(SD3_RXDP)
CPNX_SD3_TXDN: C71.2 J2.6
CPNX_SD3_TXDP: C70.2 J2.4
CPNX_SD_EXT0_REFCLKN: C73.2 J2.54
CPNX_SD_EXT0_REFCLKP: C72.2 J2.52
CPNX_SD_EXT1_REFCLKN: C75.2 J2.60
CPNX_SD_EXT1_REFCLKP: C74.2 J2.58
CPNX_SDQ0_REFCLKN: R86.1 U1.D10(SDQ0_REFCLKN) X3.5(CLK-)
CPNX_SDQ0_REFCLKP: R85.1 U1.E10(SDQ0_REFCLKP) X3.4(CLK+)
CPNX_UART_RX: J1.35 U1.F9(PR4B/URC_GPLL0C_IN)
CPNX_UART_TX: J1.33 U1.E6(PR3B)
CPNX_WRIO_1: J1.82 U1.G14(PL17A)
CPNX_WRIO_1N: J2.78 U1.F16(PL11B)
CPNX_WRIO_1P: J2.76 U1.E16(PL11A)
CPNX_WRIO_2: J1.84 U1.G15(PL17B)
CPNX_WRIO_2N: J2.84 U1.F15(PL10B)
CPNX_WRIO_2P: J2.82 U1.F14(PL10A)
CPNX_WRIO_3: J1.86 U1.E15(PL6B)
CPNX_WRIO_3N: J2.90 U1.G12(PL15B)
CPNX_WRIO_3P: J2.88 U1.G11(PL15A)
CPNX_WRIO_3V3_1: J1.49 U1.G6(PR15A)
CPNX_WRIO_3V3_2: J1.51 U1.G5(PR15B)
CPNX_WRIO_3V3_3: J1.53 U1.G3(PR17A)
CPNX_WRIO_3V3_4: J1.55 U1.G2(PR17B)
CPNX_WRIO_3V3_5: J1.29 U1.H7(PR19A)
CPNX_WRIO_3V3_6: J1.31 U1.H6(PR19B)
CPNX_WRIO_3V3_7: J2.97 U1.H5(PR28A/PCLKT1_2)
CPNX_WRIO_3V3_8: J2.98 U1.H4(PR28B)
CPNX_WRIO_3V3_9: J2.93 U1.H3(PR29A/PCLKT1_1)
CPNX_WRIO_3V3_10: J2.95 U1.H2(PR29B)
CPNX_WRIO_3V3_11: J2.87 U1.G1(PR31A/PCLKT1_0)
CPNX_WRIO_3V3_12: J2.89 U1.H1(PR31B)
CPNX_WRIO_3V3_13: J1.75 U1.F6(PR8A)
CPNX_WRIO_3V3_14: J1.56 U1.E3(PR10A)
CPNX_WRIO_3V3_15: J1.64 U1.D1(PT142B/MCSNO/MSDO)
CPNX_WRIO_3V3_16: J1.66 U1.C2(PT144A)
CPNX_WRIO_3V3_17: J1.77 U1.C1(PT144B)
CPNX_WRIO_4: J1.69 U1.E14(PL6A)
CPNX_WRIO_4N: J2.96 U1.G10(PL13B)
CPNX_WRIO_4P: J2.94 U1.G9(PL13A)
CPNX_WRIO_5: J1.19 U1.H11(PL29A/PCLKT7_1)
CPNX_WRIO_6: J1.21 U1.H10(PL28B)
CPNX_WRIO_7: J1.23 U1.F11(PL8A)
CPNX_WRIO_8: J1.25 U1.F12(PL8B)
CPNX_XO3D_PMU_WAKEUPN: U1.F1(PR13B/PMU_WAKEUPN) U12.J4(PB29B/PCLKC2_1)
ETH_GPIO_0: J1.60 U1.H14(PL31A/PCLKT7_0)
ETH_GPIO_1: J1.62 U1.H15(PL31B)
ETH_MDC: J1.30 U1.L11(PB46B/PCLKC5_3)
ETH_MDIO: J1.32 R68.2 U1.P13(PB32A)
ETH_RESET: J1.54 U1.R12(PB42B)
ETH_RGMII_RX_0: J1.20 U1.L14(PB26B)
ETH_RGMII_RX_1: J1.22 U1.M14(PB28A)
ETH_RGMII_RX_2: J1.24 U1.K13(PB34A)
ETH_RGMII_RX_3: J1.26 U1.L13(PB34B)
ETH_RGMII_RX_CLK: J1.36 U1.L12(PB46A/PCLKT5_3)
ETH_RGMII_RX_CTRL: J1.34 U1.M13(PB28B)
ETH_RGMII_TX_0: J1.40 U1.T13(PB36A)
ETH_RGMII_TX_1: J1.42 U1.R13(PB36B)
ETH_RGMII_TX_2: J1.44 U1.T14(PB30B)
ETH_RGMII_TX_3: J1.46 U1.R14(PB30A)
ETH_RGMII_TX_CLK: J1.50 U1.P12(PB40A/PCLKT5_2)
ETH_RGMII_TX_CTRL: J1.52 U1.R15(PB12B)
HR1_CKN: U1.M3(PB154B/PCLKC3_3/ADC_CN15) U4.B1(CK#)
HR1_CKP: U1.N3(PB154A/PCLKT3_3/ADC_CP15) U4.B2(CK)
HR1_CSN: R14.2 U1.T5(PB114B/COMP1IN) U4.A3(CS#)
HR1_DQ0: U1.M4(PB116B/ADC_CN8) U4.D3(DQ0)
HR1_DQ1: U1.N5(PB120B/ADC_CN13) U4.D2(DQ1)
HR1_DQ2: U1.L5(PB118B/PCLKC3_1/COMP2IN) U4.C4(DQ2)
HR1_DQ3: U1.M5(PB116A/ADC_CP8) U4.D4(DQ3)
HR1_DQ4: U1.N4(PB120A/ADC_CP13) U4.D5(DQ4)
HR1_DQ5: U1.L6(PB118A/PCLKT3_1/COMP2IP) U4.E3(DQ5)
HR1_DQ6: U1.T6(PB112B/PCLKC3_0/ADC_CN4) U4.E2(DQ6)
HR1_DQ7: U1.R6(PB112A/PCLKT3_0/ADC_CP4) U4.E1(DQ7)
HR1_RST: R15.2 U1.K5(PB110B/ADC_CN10) U4.A4(RESET#)
HR1_RWDS: U1.R5(PB114A/COMP1IP) U4.C3(RWDS)
HR_CLK: U1.K16(PB10A/PCLKT5_1/ADC_CP2/COMP3P) U8.B2(CK)
HR_CLK#: U1.K15(PB10B/PCLKC5_1/ADC_CN2/COMP3N) U8.B1(CK#)
HR_CS: R28.2 U1.R16(PB12A) U8.A3(CS#)
HR_DQ0: U1.N16(PB4A/PCLKT5_0/CDR_RXP1/ADC_CP1/COMP2P) U8.D3(DQ0)
HR_DQ1: U1.M16(PB2A/LLC_GPLL0T_IN/CDR_RXP0/VREF5_1/ADC_CP0/COMP1P) U8.D2(DQ1)
HR_DQ2: U1.P15(PB8A/ADC_CP3) U8.C4(DQ2)
HR_DQ3: U1.N15(PB4B/PCLKC5_0/CDR_RXN1/ADC_CN1/COMP2N) U8.D4(DQ3)
HR_DQ4: U1.P16(PB8B/ADC_CN3) U8.D5(DQ4)
HR_DQ5: U1.M15(PB2B/LLC_GPLL0C_IN/CDR_RXN0/ADC_CN0/COMP1N) U8.E3(DQ5)
HR_DQ6: U1.L15(PB6B) U8.E2(DQ6)
HR_DQ7: U1.L16(PB6A) U8.E1(DQ7)
HR_RESET: R29.2 U1.P14(PB32B) U8.A4(RESET#)
HR_RWDS: U1.K14(PB26A) U8.C3(RWDS)
MIPI_27MHZ_IN: R81.2 U1.D15(PL3A/ULC_GPLL0T_IN)
MIPI_CLK_EN: R80.2 U1.H12(PL29B) X4.1(STDBY#)
PCIe_REF_CLK_EN: R76.2 U1.F7(PR6A) X3.1(OE/STDBY/FS)
PG _CPNX _EN: R63.1 U9.B2(CE) U15.3(EN) U16.4(PG) U17.3(EN)
RPI_CAM1_GPIO_0: J1.71 U1.J9(PL46A/PCLKT6_2)
RPI_CAM1_GPIO_1: J1.73 U1.J8(PL46B)
RPI_CAM_GPIO_0: J1.59 U1.J16(PL42A/PCLKT6_0)
RPI_CAM_GPIO_1: J1.61 U1.J15(PL42B)
RPI_CAM_SCL: J1.65 R93.2 U1.J11(PL44A/PCLKT6_1)
RPI_CAM_SDA: J1.63 R94.2 U1.J10(PL44B)
SD0_REFRET: C82.2 C83.2 C89.2 C90.2 R32.2 U1.C15(SD0_REFRET)
SD0_REXT: R32.1 U1.C16(SD0_REXT)
SD1_REFRET: C76.2 C77.2 C84.2 C85.2 R33.2 U1.B12(SD1_REFRET)
SD1_REXT: R33.1 U1.B13(SD1_REXT)
SD2_REFRET: C78.2 C79.2 C86.2 C87.2 R34.2 U1.D8(SD2_REFRET)
SD2_REXT: R34.1 U1.E8(SD2_REXT)
SD3_REFRET: C80.2 C81.2 C88.2 C91.2 R36.2 U1.B8(SD3_REFRET)
SD3_REXT: R36.1 U1.B6(SD3_REXT)
SERDES_LDO_EN: R39.2 R67.2 U10.B2(CE) U11.B2(CE) U12.E2(PR10C)
SPI_CS#: R3.2 U1.D4(PT138A/MCSN/PCLKT0_1) U3.1(#CS) U12.J8(PB7A/CSSPIN)
SPI_IO0: U1.D3(PT138B/MOSI/MD0) U3.5(DI_(IO0)) U12.G6(PB16B/SO/SPISO)
SPI_IO1: U1.C4(PT140A/MISO/MD1) U3.2(DO_(IO1)) U12.J1(PB46B/SI/SISPI)
SPI_IO2: R2.2 U1.C3(PT140B/MD2) U3.3(#WP_(IO2)) U12.J6(PB18A)
SPI_IO3: R4.2 U1.D2(PT142A/MD3) U3.7(#RESET_(IO3)) U12.H6(PB18B)
SPI_MCLK: R9.2 R46.1 U3.6(CLK)
TORNA_VER_0: R88.2 R90.1 U1.D16(PL3B/ULC_GPLL0C_IN)
TORNA_VER_1: R87.2 R89.1 U1.E12(PL4A)
TORNA_VER_2: R95.2 R96.1 U1.E13(PL4B)
XO3D_24MHZ_IN: R84.2 U12.D2(PR3B/R_GPLLC_IN)
XO3D_CPNX_GPIO_1: U1.J7(PR42A/PCLKT2_0) U12.G8(PL25A/I3C)
XO3D_CPNX_GPIO_2: U1.J6(PR42B) U12.F8(PL25B/I3C)
XO3D_CPNX_GPIO_3: U1.K2(PR44A/PCLKT2_1) U12.E8(PL27A/PCLKT3_0/I3C)
XO3D_CPNX_GPIO_4: U1.J2(PR44B) U12.E7(PL27B/PCLKC3_0/I3C)
XO3D_CPNX_GPIO_5: U1.K1(PR46A/PCLKT2_2) U12.F7(PL27C)
XO3D_CPNX_GPIO_6: U1.J1(PR46B) U12.F5(PL28A)
XO3D_CPNX_PROGRAMN: R74.2 U12.J5(PB22B/PCLKC2_0)
XO3D_DONE: Q2.1(GATE) R55.2 U12.A1(PT44D/DONE)
XO3D_INITN: R77.1 U12.A2(PT44C/INITN)
XO3D_JTAG_EN: J1.90 R72.2 R73.1 U12.C5(PT31C/JTAGENB)
XO3D_JTAG_TCK: J1.98 R50.1 TP16.1(TP) U12.B6(PT22C/TCK)
XO3D_JTAG_TDI: J1.94 R51.2 TP17.1(TP) U12.A6(PT15D/TDI)
XO3D_JTAG_TDO: J1.96 R52.2 TP18.1(TP) U12.B7(PT15C/TDO)
XO3D_JTAG_TMS: J1.92 R49.2 TP15.1(TP) U12.C7(PT22D/TMS)
XO3D_PROGRAMN: J1.85 R45.2 R75.2 U12.D5(PT31D/PROGRAMN)
XO3D_UART_RX: J1.81 U12.E6(PT28B)
XO3D_UART_TX: J1.83 U12.D6(PT28A)
XO3D_WRIO_0: J1.70 U12.H1(PR28A)
XO3D_WRIO_1: J1.72 U12.G1(PR24A)
XO3D_WRIO_2: J1.74 U12.G2(PR24B)
XO3D_WRIO_3: J1.76 U12.F3(PR17B/PCLKC1_0)
XO3D_WRIO_4: J1.78 U12.F2(PR17A/PCLKT1_0)
N17783249: C124.2 R57.1 R61.1 U15.8(FB)
N17784177: C121.2 R58.2 R62.1 U16.8(FB)
N17784623: C125.2 R59.2 R64.1 U17.8(FB)
N17787550: R9.1 U1.E5(PT136A/MCLK/PCLKT0_0)
N17789742: C56.1 U1.A15(SD0_TXDP)
N17789745: C57.1 U1.A14(SD0_TXDN)
N17789748: C60.1 U1.A12(SD1_TXDP)
N17789752: C61.1 U1.A11(SD1_TXDN)
N17789780: C68.1 U1.A9(SD2_TXDP)
N17789783: C69.1 U1.A8(SD2_TXDN)
N17789786: C70.1 U1.A6(SD3_TXDP)
N17789789: C71.1 U1.A5(SD3_TXDN)
N17790838: R40.2 R42.1 U10.B1(VFB)
N17791141: R41.2 R43.1 U11.B1(VFB)
N17797461: C72.1 R35.1 U1.B2(SD_EXT0_REFCLKP)
N17797464: C73.1 R35.2 U1.B3(SD_EXT0_REFCLKN)
N17797467: C74.1 R37.1 U1.A2(SD_EXT1_REFCLKP)
N17797470: C75.1 R37.2 U1.B1(SD_EXT1_REFCLKN)
N17812965: D5.A(ANODE) R56.2
N17818332: R47.1 U14.B1(EN)
N17818352: C106.1 R44.1 U13.B1(EN)
N17864782: C39.1 FB1.1 R27.2 X1.4(VDD)
N17864920: R27.1 X1.1(OE)
N17864958: R82.1 X1.3(OUT)
N17868035: R30.2 R31.1 U9.B1(VFB)
N17900201: D1.A(ANODE) R1.1
N17902884: D3.A(ANODE) R48.1
N17910978: R46.2 U12.G5(PB16A/MCLK/CCLK)
N17922161: FB2.1 U1.P1(VCCADC18)
N18051803: C148.1 C149.1 FB13.2 R80.1 X4.4(VDD)
N18051855: R81.1 X4.3(OUT)
N18079491: C150.1 C151.1 FB14.2 R83.1 X5.4(VDD)
N18079497: R83.2 X5.1(STDBY#)
N18079566: R84.1 X5.3(OUT)
N18094301: D3.K(CATHODE) Q2.3(DRAIN)
N18209175: D1.K(CATHODE) Q1.3(DRAIN)

Not connected (* = marked no-connect by the designer): U1 G16(PL19A)* H9(PL28A/PCLKT7_2)* H16(PL19B)* P11(PB40B/PCLKC5_2)* R7(PB104B/ADC_CN9)* T7(PB104A/ADC_CP9)* T12(PB42A)*; U4 A2(RFU1)* A5(RFU2)* B5(RFU3)* C2(RFU4)* C5(RFU5)*; U8 A2(RFU1) A5(RFU2) B5(RFU3) C2(RFU4) C5(RFU5); U12 A3(PT38A) A5(PT23B/PCLKC0_1) A7(PT11B) A8(PT11A) B1(PR2C) B2(PR2A/R_GPLLT_FB) B3(PT38B) B5(PT23A/PCLKT0_1) C2(PR2B/R_GPLLC_FB) C3(PR3A/R_GPLLT_IN) C4(PT39B) C6(PT27C/SCL) D1(PR5A) D4(PT39A) D7(PT27D/SDA) E1(PR10D) F6(PL28B) G3(PB41A) G7(PL28C) H2(PB41B) H3(PB35A) H7(PL28D) J2(PB46A/SN) J3(PB35B) J7(PB7B); U15 4(PG)*; U17 4(PG)*; X3 2(NC)

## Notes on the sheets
sheet 1
- LFCPNX-SOM-EVN
- Rev - C
- 01 - Title Page
  02 - Block Diagram
  03- CPNX_Bank_0 &3
  04- CPNX_Bank_1 &2
  05- CPNX_Bank_4,5,6
  06- CPNX_SERDES
  07- Connector
  08- XO3D FPGA
  09- Power Supply
  10- Power Diagram
sheet 2
- BLOCK DIAGRAM
sheet 3
- FPGA CONFIGURATION
- WRIO
  Bank-0
  3.3V
- HYPERRAM INTERFACE
- HPIO
  Bank-3
  1.8V
sheet 4
- JTAG , TEMP SENS & WRIO  INTERFACE
- I2C ADDR: 0x48
- WRIO
  Bank-7
  1.8V
- WRIO
  Bank-1
  3.3V
- I2C ADDR: 0x49
- CLOCK &  ADC INTERFACE
- Bank-6
- WRIO
  Bank-2
  3.3V
- ADC
  1.8V
sheet 5
- CPNX HyperRAM INTERFACE
- HPIO
  Bank-5
  1.8V
- MIPI CAMERA INTERFACE
- VSET=VFBx((R1+R2)/R2)
  VSET=0.6Vx((20K+20K)/20)
  VSET=1.2V
- HPIO
  Bank-4
  1.2V
- 27MHz Clock
- OSCILLATOR
sheet 6
- SERDES
- Serdes
- SERDES POWER
- VSET=VFBx((R1+R2)/R2)
  VSET=0.6Vx((20.5K+10K)/10k)
  VSET=1.83V
- VSET=VFBx((R1+R2)/R2)
  VSET=0.6Vx((15K+20K)/20K)
  VSET=1.05V
sheet 7
- 100-PIN CONNECTOR
- R97 Mount only when SOM
  used standalone
- Board Version Control
sheet 8
- XO3D FPGA
- Power Sequence XO3D: For HE devices,
  VCC needs to be powered up prior to
  VCCIOx by at least 20 ms.
- 24MHz Clock
- OSCILLATOR
sheet 9
- POWER SUPPLY
- R1= R2 x ((Vout/0.6V)-1)
  R1=100Kx((1.8V/0.6V)-1)
  R1=200K
- R1= R2 x ((Vout/0.6V)-1)
  R1=100Kx((1.0V/0.6V)-1)
  R1=66.5K
- R1= R2 x ((Vout/0.6V)-1)
  R1=100Kx((3.3V/0.6V)-1)
  R1=453K
- FPGA CORE POWER & GND
sheet 10
- CLOCK Diagram
- POWER TREE
